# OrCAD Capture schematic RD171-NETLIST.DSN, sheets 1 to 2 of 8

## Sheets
1 8: size A3
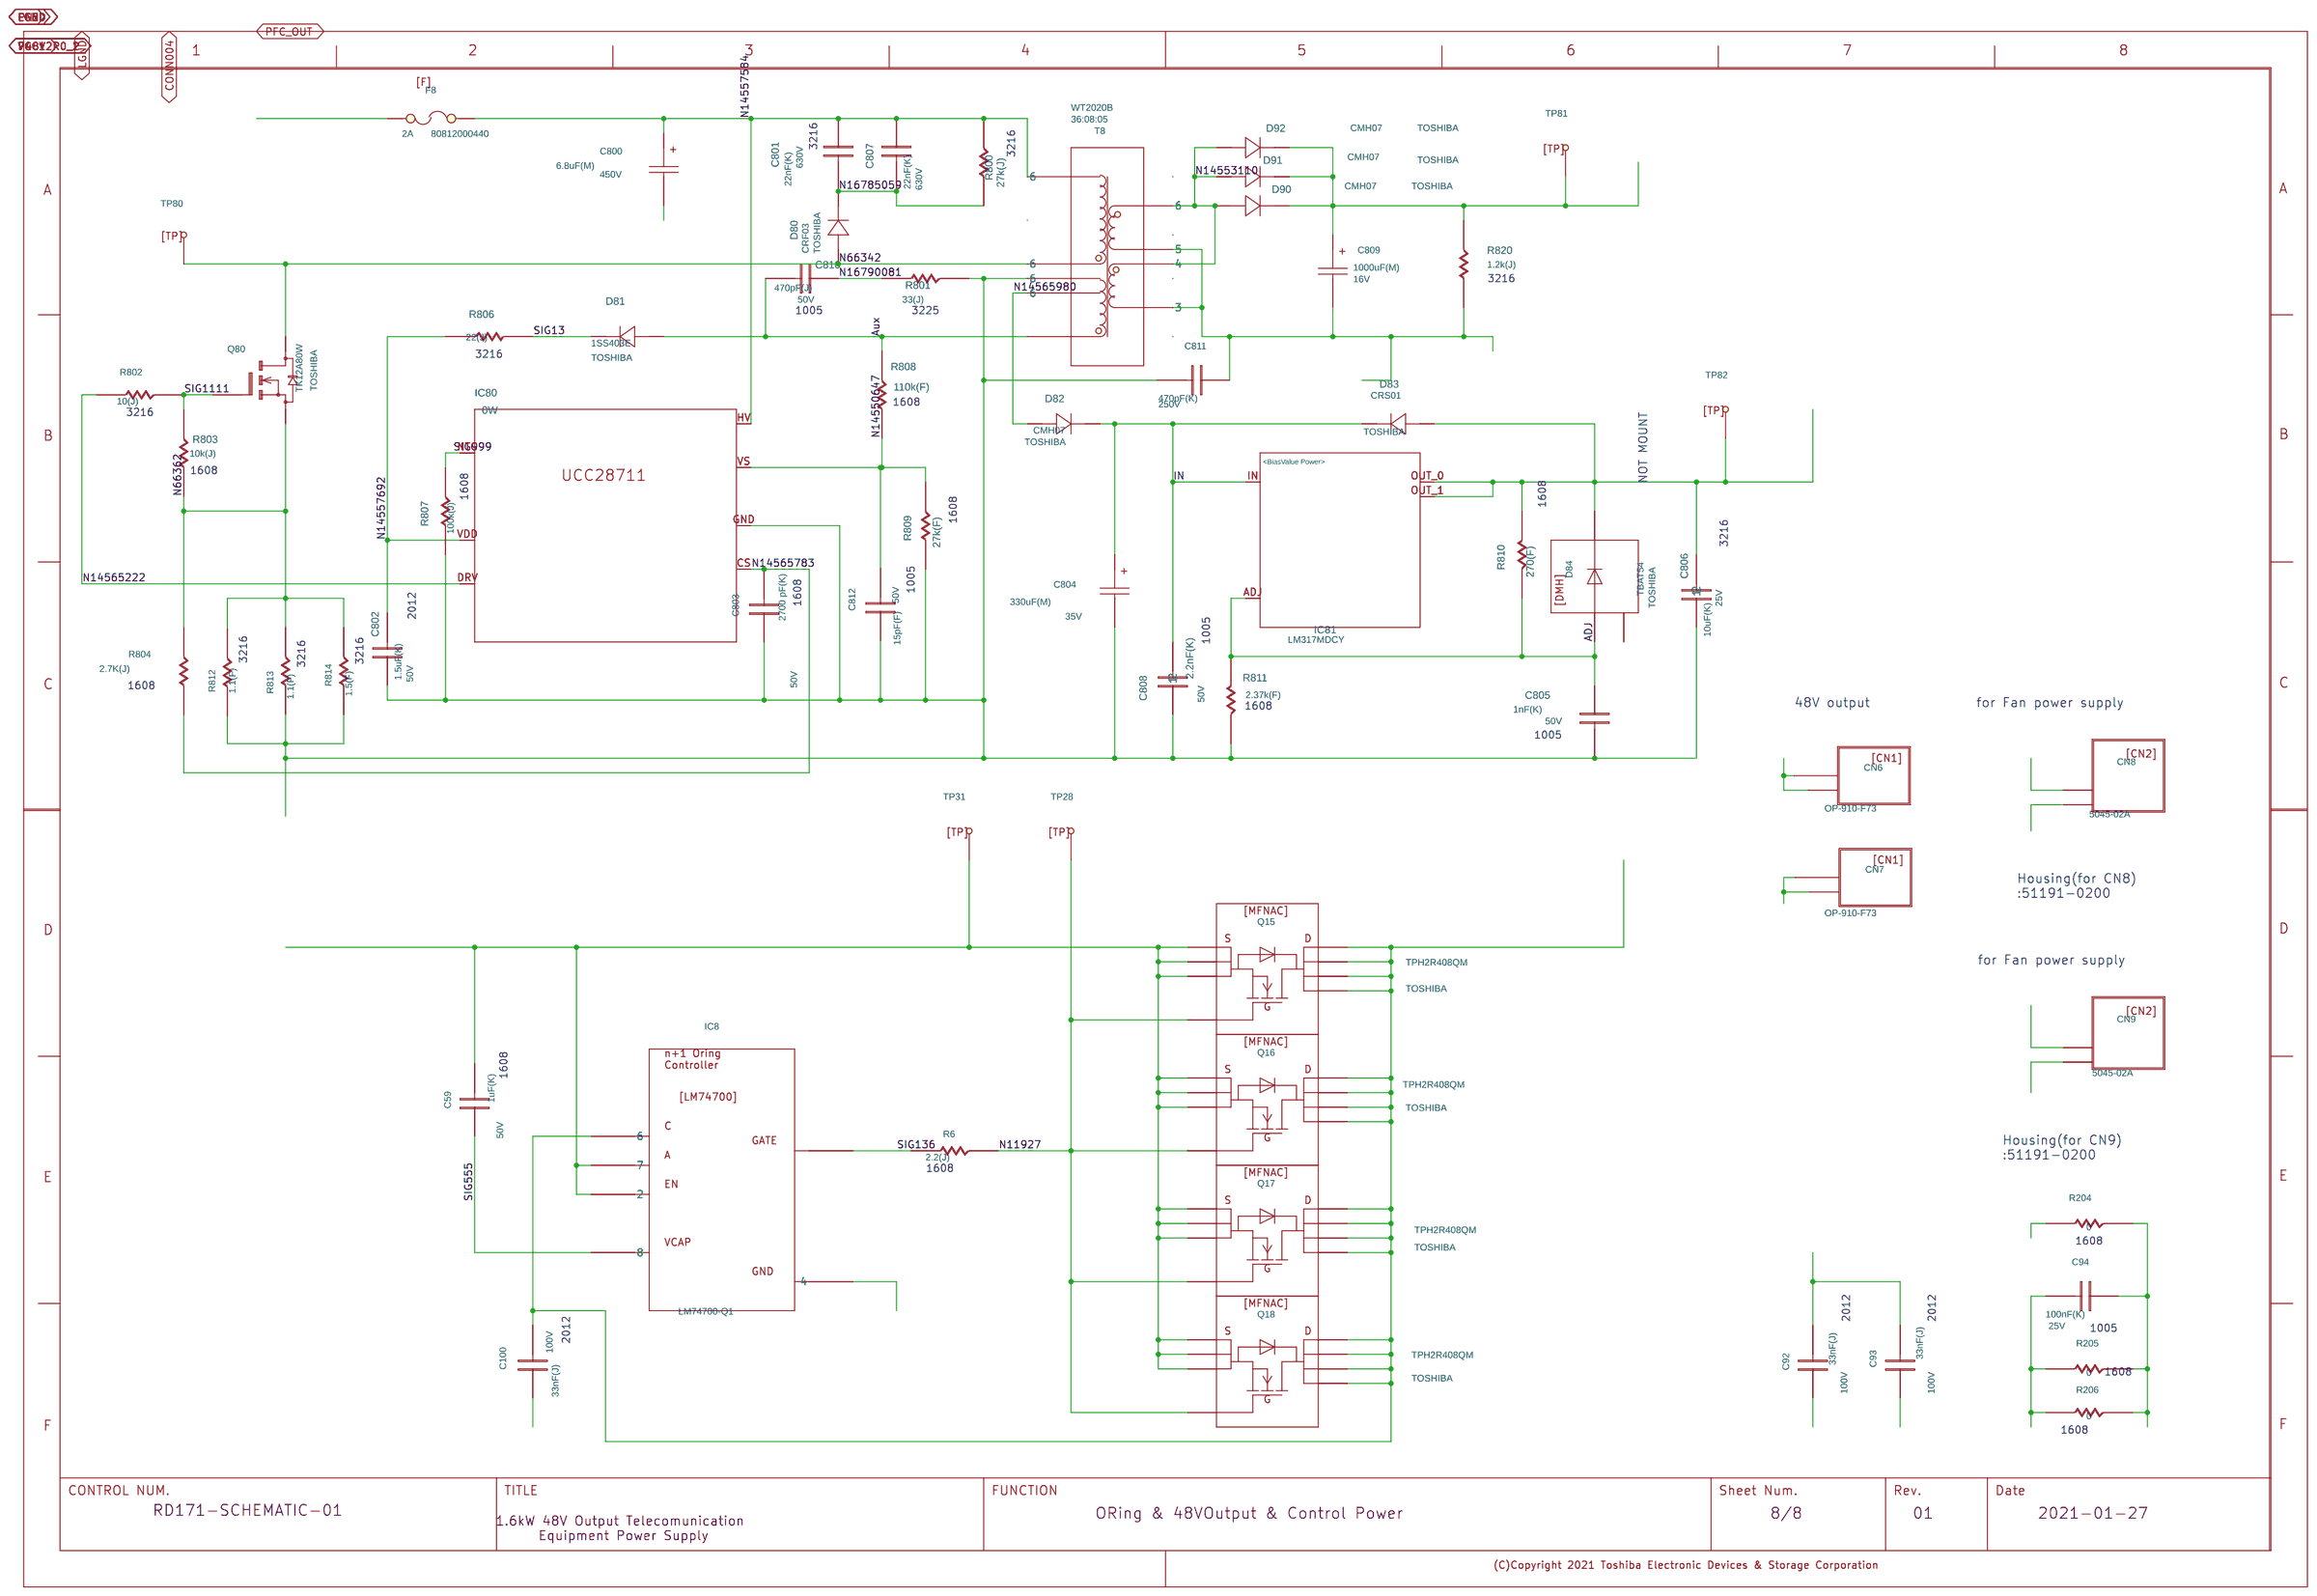
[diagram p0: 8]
2 7: size A3
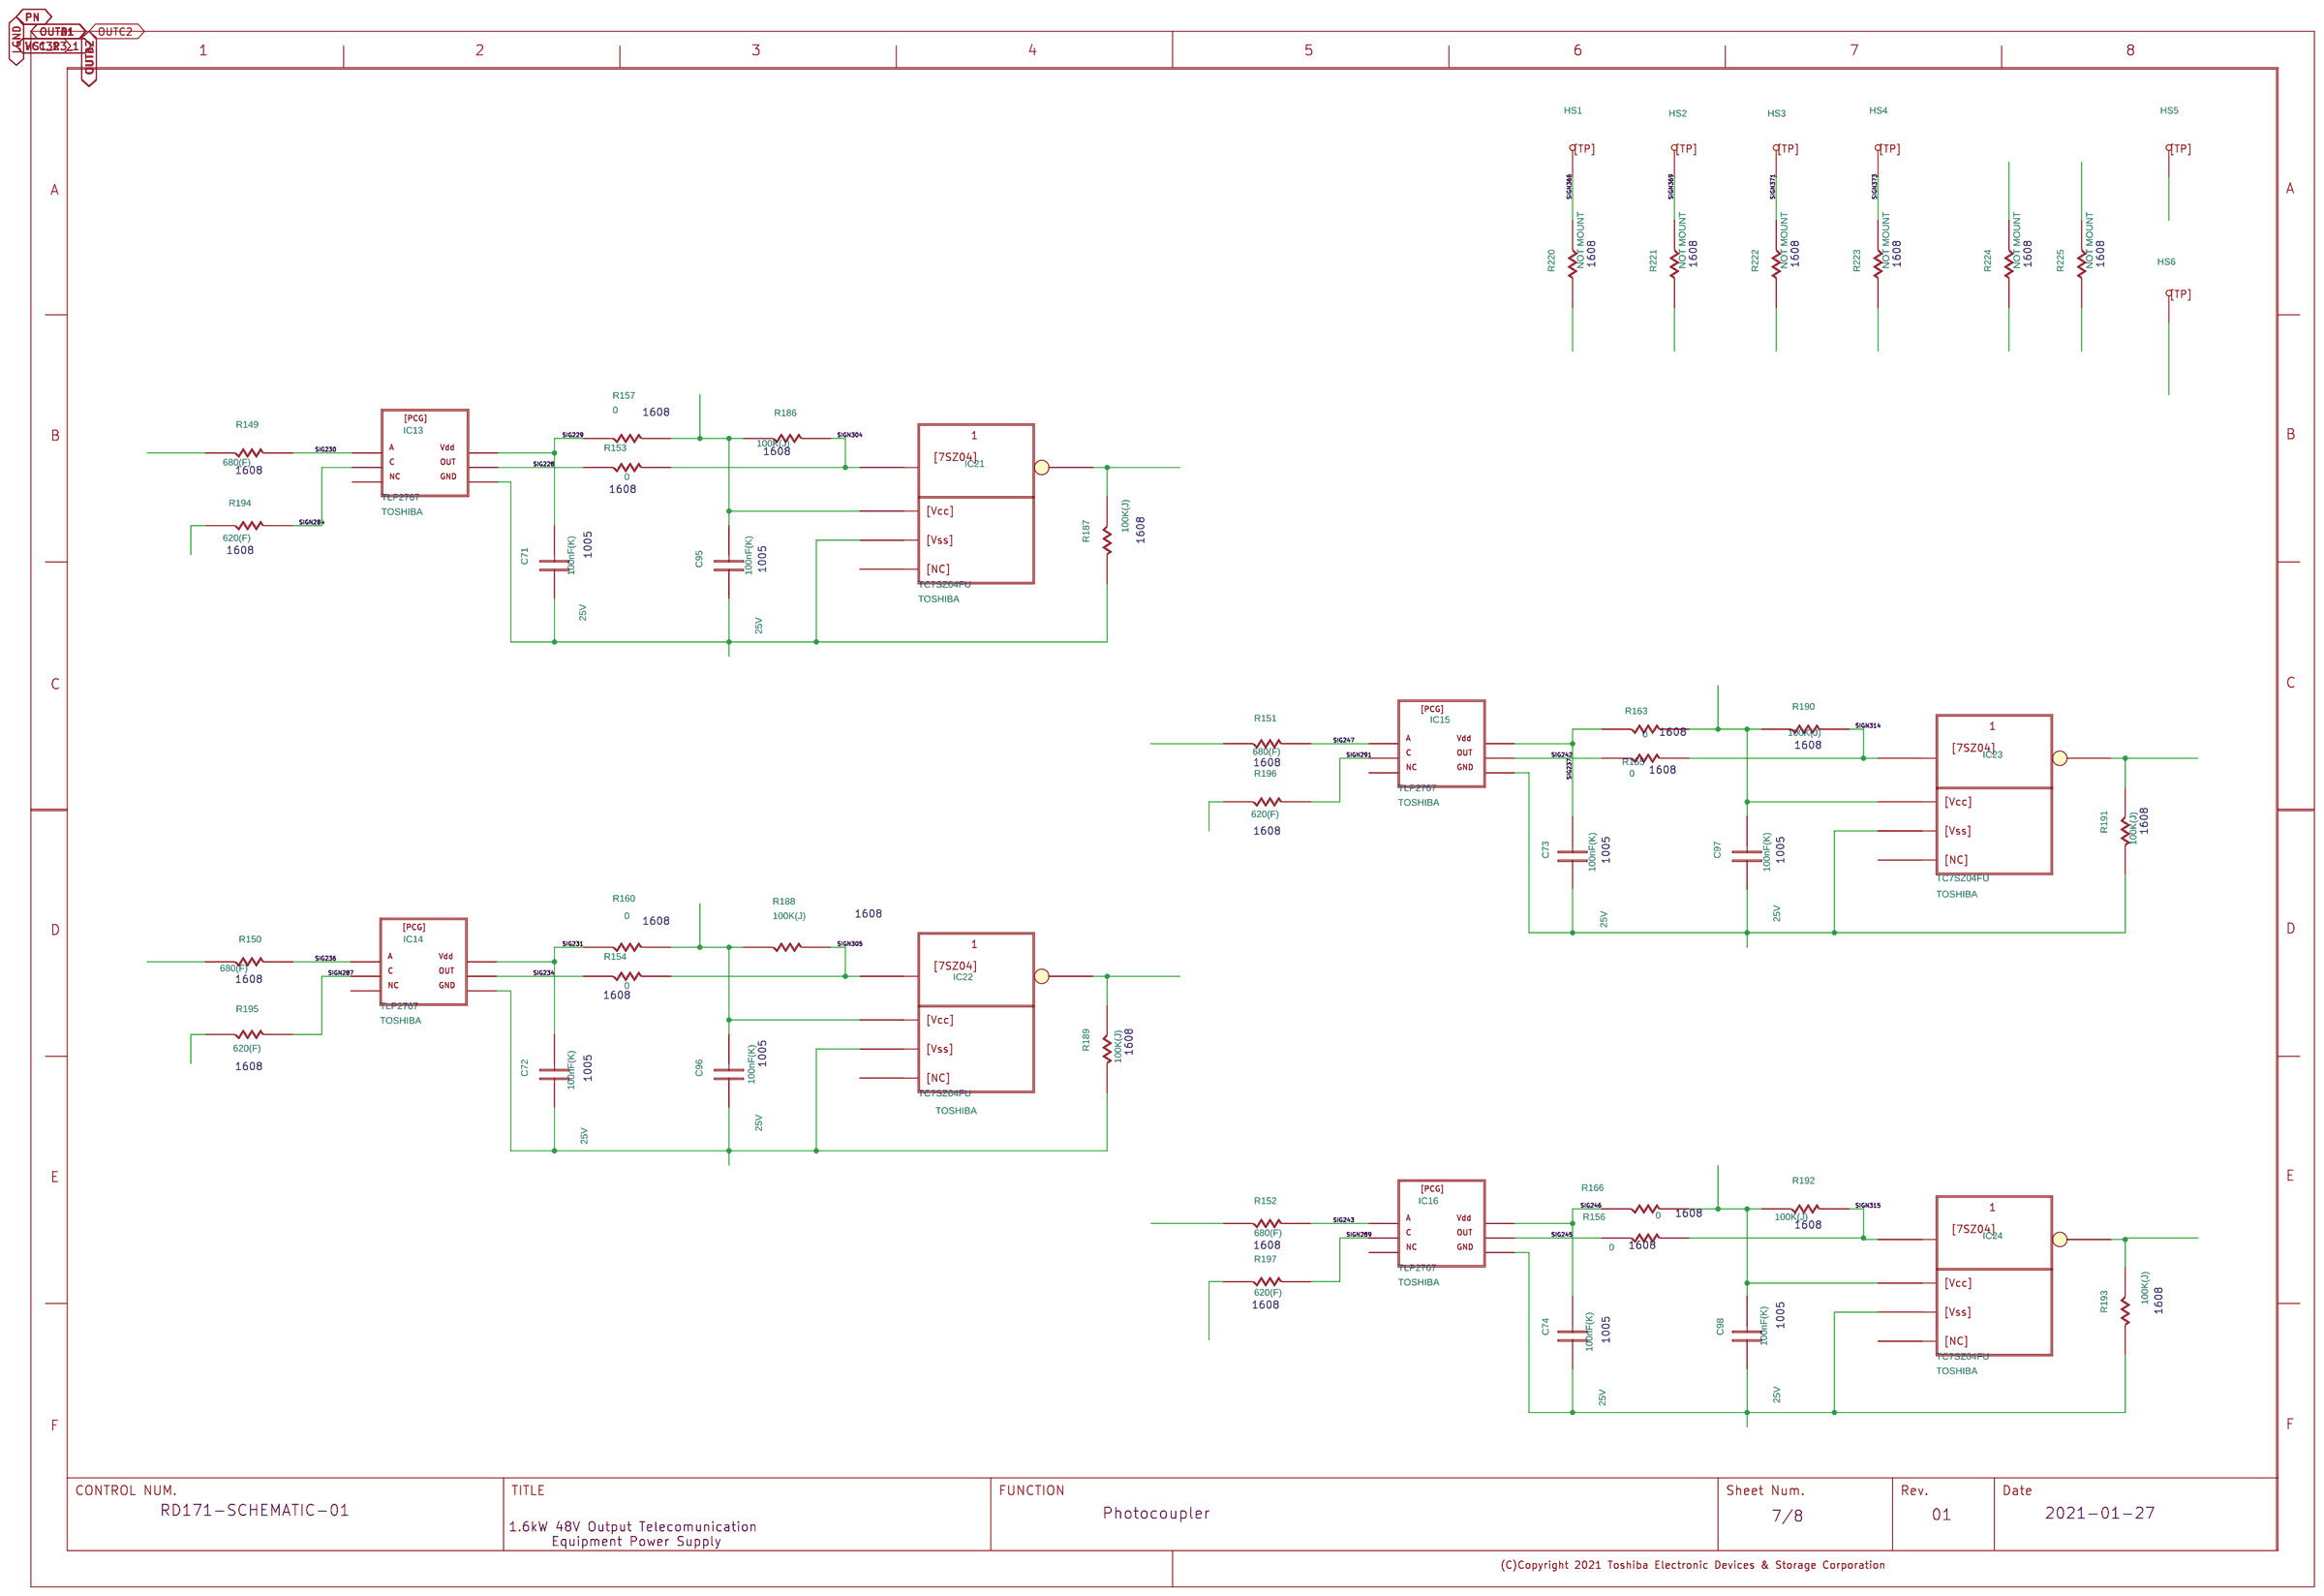
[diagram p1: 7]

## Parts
sheet 7
C71  100nF
C72  100nF
C73  100nF
C74  100nF
C95  100nF
C96  100nF
C97  100nF
C98  100nF
HS1  HS1  [HOLE2.8]
HS2  HS2  [HOLE2.8]
HS3  HS3  [HOLE2.8]
HS4  HS4  [HOLE2.8]
HS5  HS5  [HOLE2.0]
HS6  HS5  [HOLE2.0]
IC13  IC13  [TLP2767]
IC14  IC14  [TLP2767]
IC15  IC15  [TLP2767]
IC16  IC16  [TLP2767]
IC21  IC21  [TC7SZ04FU]
IC22  IC22  [TC7SZ04FU]
IC23  IC23  [TC7SZ04FU]
IC24  IC24  [TC7SZ04FU]
R149  680
R150  680
R151  680
R152  680
R153  0
R154  0
R155  0
R156  0
R157  0
R160  0
R163  0
R166  0
R186  100k
R187  100k
R188  100k
R189  100k
R190  100k
R191  100k
R192  100k
R193  100k
R194  620
R195  620
R196  620
R197  620
R220  0
R221  0
R222  0
R223  0
R224  0
R225  0
U?#1  WAKU_DEF100
sheet 8
C59  1uF  [C1608JB1H105K080AB]
C92  33nF  [C2012C0G2A333J125AE]
C93  33nF  [C2012C0G2A333J125AE]
C94  100nF
C100  33nF  [C2012C0G2A333J125AE]
C800  6.8uF  [EKXJ451ETD6R8MJ16S]
C801  22nF  [C3216X7R2J223K130AA]
C802  1.5uF  [C2012X7R1H155K125AC]
C803  2.7nF
C804  330uF  [EKZH350ETD331MJC5S]
C805  1nF
C806  10uF  [C3216X7R1E106K160AE]
C807  22nF  [C3216X7R2J223K130AA]
C808  2.2nF
C809  1000uF  [EKZH160ELL102MH20D]
C810  470pF  [C1005NP01H471J050BA]
C811  470pF  [DE2B3SA471KN3AT02F]
C812  NOT MOUNT
CN6  CN6  [OP-910-F73]
CN7  CN7
CN8  CN8  [5045-02A]
CN9  CN9  [5045-02A]
D80  D80  [CRF03]
D81  D81  [1SS403E]
D82  D82  [CMH07]
D83  D83  [CRS01]
D84  D84  [TBAT54]
D90  D90  [CMH07]
D91  D91  [CMH07]
D92  D92  [CMH07]
F8  2A  [80812000440]
IC8  IC8  [LM74700-Q1]
IC80  IC80  [UCC28711DR]
IC81  LM317_TRANS  [LM317MDCY]
Q15  Q15  [TPH2R408QM]
Q16  Q16  [TPH2R408QM]
Q17  Q17  [TPH2R408QM]
Q18  Q18  [TPH2R408QM]
Q80  Q80  [TK12A80W]
R6  2.2
R204  0
R205  0
R206  0
R800  27k  [MOS3CT631R273J]
R801  33  [RK73B2ETTD330J]
R802  10
R803  10k
R804  2.7k
R806  22
R807  100k
R808  110k
R809  27k
R810  270
R811  2.37k
R812  1.1  [RK73H2BTTD1R10F]
R813  1.1  [RK73H2BTTD1R10F]
R814  1.5  [RK73H2BTTD1R50F]
R820  1.2k
T8  T3_12V67A
TP28  TP28  [HK-2-S]
TP31  TP31  [HK-2-S]
TP80  TP80  [HK-2-S]
TP81  TP81  [HK-2-S]
TP82  TP82  [HK-2-S]
U?#8  WAKU_DEF100

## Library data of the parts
C71 = C: ADSCNVFLAG: ON; ADSCOMPONENTNAME: C_1005; ADSMODELNAME: s_GRM155R71E104KE14D; CAPACITANCETOLE: K; CDMASTERCADCELG: KC0005; CHIPSIZE: 1005; COMP: PRT_52; COMPONENTNAME: C_C.Normal_package; FNLEADFREETHET1GT2GMCTH1: N_N_N; FUNCTION: C_C.Normal_package; GCOUNT: 1; ICX_PART_MODEL: CON_100N; INSTANCENAME: INS10182; MAKER: TDK; MAXGCOUNT: 1; NOMINALCAPACITA: 100n; OUMECLASSIFICATION: ƒZƒ‰ƒ~ƒbƒNƒRƒ“ƒfƒ“ƒT; OUMEMAKER: MRT ºc»ì; OUMEMAKERKATAMEI: GRM155R71E104KE14D; PARTNAME: Chip1005_GS_2; QUADMODEL: CON_100N; RATEDVOLTAGE: 25; SIZECODESMD: 1005; SQ_PART_MODEL: CON_100N; VAL1: 100nF(K); VAL2: 25V; VAL3: C1005X7R1E104K050BB
C72 = C: ADSCNVFLAG: ON; ADSCOMPONENTNAME: C_1005; ADSMODELNAME: s_GRM155R71E104KE14D; CAPACITANCETOLE: K; CDMASTERCADCELG: KC0005; CHIPSIZE: 1005; COMP: PRT_52; COMPONENTNAME: C_C.Normal_package; FNLEADFREETHET1GT2GMCTH1: N_N_N; FUNCTION: C_C.Normal_package; GCOUNT: 1; ICX_PART_MODEL: CON_100N; INSTANCENAME: INS10192; MAKER: TDK; MAXGCOUNT: 1; NOMINALCAPACITA: 100n; OUMECLASSIFICATION: ƒZƒ‰ƒ~ƒbƒNƒRƒ“ƒfƒ“ƒT; OUMEMAKER: MRT ºc»ì; OUMEMAKERKATAMEI: GRM155R71E104KE14D; PARTNAME: Chip1005_GS_2; QUADMODEL: CON_100N; RATEDVOLTAGE: 25; SIZECODESMD: 1005; SQ_PART_MODEL: CON_100N; VAL1: 100nF(K); VAL2: 25V; VAL3: C1005X7R1E104K050BB
C73 = C: ADSCNVFLAG: ON; ADSCOMPONENTNAME: C_1005; ADSMODELNAME: s_GRM155R71E104KE14D; CAPACITANCETOLE: K; CDMASTERCADCELG: KC0005; CHIPSIZE: 1005; COMP: PRT_52; COMPONENTNAME: C_C.Normal_package; FNLEADFREETHET1GT2GMCTH1: N_N_N; FUNCTION: C_C.Normal_package; GCOUNT: 1; ICX_PART_MODEL: CON_100N; INSTANCENAME: INS10222; MAKER: TDK; MAXGCOUNT: 1; NOMINALCAPACITA: 100n; OUMECLASSIFICATION: ƒZƒ‰ƒ~ƒbƒNƒRƒ“ƒfƒ“ƒT; OUMEMAKER: MRT ºc»ì; OUMEMAKERKATAMEI: GRM155R71E104KE14D; PARTNAME: Chip1005_GS_2; QUADMODEL: CON_100N; RATEDVOLTAGE: 25; SIZECODESMD: 1005; SQ_PART_MODEL: CON_100N; VAL1: 100nF(K); VAL2: 25V; VAL3: C1005X7R1E104K050BB
C74 = C: ADSCNVFLAG: ON; ADSCOMPONENTNAME: C_1005; ADSMODELNAME: s_GRM155R71E104KE14D; CAPACITANCETOLE: K; CDMASTERCADCELG: KC0005; CHIPSIZE: 1005; COMP: PRT_52; COMPONENTNAME: C_C.Normal_package; FNLEADFREETHET1GT2GMCTH1: N_N_N; FUNCTION: C_C.Normal_package; GCOUNT: 1; ICX_PART_MODEL: CON_100N; INSTANCENAME: INS10252; MAKER: TDK; MAXGCOUNT: 1; NOMINALCAPACITA: 100n; OUMECLASSIFICATION: ƒZƒ‰ƒ~ƒbƒNƒRƒ“ƒfƒ“ƒT; OUMEMAKER: MRT ºc»ì; OUMEMAKERKATAMEI: GRM155R71E104KE14D; PARTNAME: Chip1005_GS_2; QUADMODEL: CON_100N; RATEDVOLTAGE: 25; SIZECODESMD: 1005; SQ_PART_MODEL: CON_100N; VAL1: 100nF(K); VAL2: 25V; VAL3: C1005X7R1E104K050BB
C95 = C: ADSCOMPONENTNAME: C_1005; ADSMODELNAME: s_GRM155R71E104KE14D; CAPACITANCETOLE: K; CHIPSIZE: 1005; COMP: PRT_52; COMPONENTNAME: C_C.Normal_package; FUNCTION: C_C.Normal_package; GCOUNT: 1; INSTANCENAME: INS10380; MAKER: TDK; MAXGCOUNT: 1; NOMINALCAPACITA: 100n; PARTNAME: Chip1005_GS_2; RATEDVOLTAGE: 25; SIZECODESMD: 1005; VAL1: 100nF(K); VAL2: 25V; VAL3: C1005X7R1E104K050BB
C96 = C: ADSCOMPONENTNAME: C_1005; ADSMODELNAME: s_GRM155R71E104KE14D; CAPACITANCETOLE: K; CHIPSIZE: 1005; COMP: PRT_52; COMPONENTNAME: C_C.Normal_package; FUNCTION: C_C.Normal_package; GCOUNT: 1; INSTANCENAME: INS10448; MAKER: TDK; MAXGCOUNT: 1; NOMINALCAPACITA: 100n; PARTNAME: Chip1005_GS_2; RATEDVOLTAGE: 25; SIZECODESMD: 1005; VAL1: 100nF(K); VAL2: 25V; VAL3: C1005X7R1E104K050BB
C97 = C: ADSCOMPONENTNAME: C_1005; ADSMODELNAME: s_GRM155R71E104KE14D; CAPACITANCETOLE: K; CHIPSIZE: 1005; COMP: PRT_52; COMPONENTNAME: C_C.Normal_package; FUNCTION: C_C.Normal_package; GCOUNT: 1; INSTANCENAME: INS10544; MAKER: TDK; MAXGCOUNT: 1; NOMINALCAPACITA: 100n; PARTNAME: Chip1005_GS_2; RATEDVOLTAGE: 25; SIZECODESMD: 1005; VAL1: 100nF(K); VAL2: 25V; VAL3: C1005X7R1E104K050BB
C98 = C: ADSCOMPONENTNAME: C_1005; ADSMODELNAME: s_GRM155R71E104KE14D; CAPACITANCETOLE: K; CHIPSIZE: 1005; COMP: PRT_52; COMPONENTNAME: C_C.Normal_package; FUNCTION: C_C.Normal_package; GCOUNT: 1; INSTANCENAME: INS10534; MAKER: TDK; MAXGCOUNT: 1; NOMINALCAPACITA: 100n; PARTNAME: Chip1005_GS_2; RATEDVOLTAGE: 25; SIZECODESMD: 1005; VAL1: 100nF(K); VAL2: 25V; VAL3: C1005X7R1E104K050BB
HS1 = TP: CHIPSIZE: Through Hole; COMP: PRT_39; COMPONENTNAME: TP_TP.Normal_package; FUNCTION: TP_TP.Normal_package; INSTANCENAME: INS10726; PARTNAME: TP_I_TH2.8_TBLC3.8_ILC0_RC3.9_GS
HS2 = TP: CHIPSIZE: Through Hole; COMP: PRT_39; COMPONENTNAME: TP_TP.Normal_package; FUNCTION: TP_TP.Normal_package; INSTANCENAME: INS10734; PARTNAME: TP_I_TH2.8_TBLC3.8_ILC0_RC3.9_GS
HS3 = TP: CHIPSIZE: Through Hole; COMP: PRT_39; COMPONENTNAME: TP_TP.Normal_package; FUNCTION: TP_TP.Normal_package; INSTANCENAME: INS10742; PARTNAME: TP_I_TH2.8_TBLC3.8_ILC0_RC3.9_GS
HS4 = TP: CHIPSIZE: Through Hole; COMP: PRT_39; COMPONENTNAME: TP_TP.Normal_package; FUNCTION: TP_TP.Normal_package; INSTANCENAME: INS10750; PARTNAME: TP_I_TH2.8_TBLC3.8_ILC0_RC3.9_GS
HS5 = TP: CHIPSIZE: Through Hole; COMP: PRT_39; COMPONENTNAME: TP_TP.Normal_package; FUNCTION: TP_TP.Normal_package; INSTANCENAME: INS17030042; PARTNAME: BPUS15-25_GS; VAL3: BPUS15-25
HS6 = TP: CHIPSIZE: Through Hole; COMP: PRT_39; COMPONENTNAME: TP_TP.Normal_package; FUNCTION: TP_TP.Normal_package; INSTANCENAME: INS17030123; PARTNAME: BPUS15-25_GS; VAL3: BPUS15-25
IC13 = PCG6PIN: COMP: PRT_15; COMPONENTNAME: PCG6PIN_PCG6PIN.Normal_package; FUNCTION: PCG6PIN_PCG6PIN.Normal_package; INSTANCENAME: INS10674; MAKER: TOSHIBA; PARTNAME: TLP2767_TS; USERCOMPTEXT3: TOSHIBA
IC14 = PCG6PIN: COMP: PRT_15; COMPONENTNAME: PCG6PIN_PCG6PIN.Normal_package; FUNCTION: PCG6PIN_PCG6PIN.Normal_package; INSTANCENAME: INS10614; MAKER: TOSHIBA; PARTNAME: TLP2767_TS; USERCOMPTEXT3: TOSHIBA
IC15 = PCG6PIN: COMP: PRT_15; COMPONENTNAME: PCG6PIN_PCG6PIN.Normal_package; FUNCTION: PCG6PIN_PCG6PIN.Normal_package; INSTANCENAME: INS10634; MAKER: TOSHIBA; PARTNAME: TLP2767_TS; USERCOMPTEXT3: TOSHIBA
IC16 = PCG6PIN: COMP: PRT_15; COMPONENTNAME: PCG6PIN_PCG6PIN.Normal_package; FUNCTION: PCG6PIN_PCG6PIN.Normal_package; INSTANCENAME: INS10654; MAKER: TOSHIBA; PARTNAME: TLP2767_TS; USERCOMPTEXT3: TOSHIBA
IC21 = 7SZ04: COMP: PRT_2; COMPONENTNAME: 7SZ04_7SZ04.Normal_package; FUNCTION: 7SZ04_7SZ04.Normal_package; INSTANCENAME: INS10362; MAKER: TOSHIBA; PARTNAME: TC7SZ04FU_TS_1; SAVECOUNT: 1; UPDATEDATE: 2020/07/08; UPDATETIME: 16:40:05; USERCOMPTEXT3: TOSHIBA
IC22 = 7SZ04: COMP: PRT_2; COMPONENTNAME: 7SZ04_7SZ04.Normal_package; FUNCTION: 7SZ04_7SZ04.Normal_package; INSTANCENAME: INS10420; MAKER: TOSHIBA; PARTNAME: TC7SZ04FU_TS_1; SAVECOUNT: 1; UPDATEDATE: 2020/07/08; UPDATETIME: 16:40:05; USERCOMPTEXT3: TOSHIBA
IC23 = 7SZ04: COMP: PRT_2; COMPONENTNAME: 7SZ04_7SZ04.Normal_package; FUNCTION: 7SZ04_7SZ04.Normal_package; INSTANCENAME: INS10468; MAKER: TOSHIBA; PARTNAME: TC7SZ04FU_TS_1; SAVECOUNT: 1; UPDATEDATE: 2020/07/08; UPDATETIME: 16:40:05; USERCOMPTEXT3: TOSHIBA
IC24 = 7SZ04: COMP: PRT_2; COMPONENTNAME: 7SZ04_7SZ04.Normal_package; FUNCTION: 7SZ04_7SZ04.Normal_package; INSTANCENAME: INS10516; MAKER: TOSHIBA; PARTNAME: TC7SZ04FU_TS_1; SAVECOUNT: 1; UPDATEDATE: 2020/07/08; UPDATETIME: 16:40:05; USERCOMPTEXT3: TOSHIBA
R149 = R: CHIPSIZE: 1608; COMP: PRT_8; COMPONENTNAME: R_R.Normal_package; FUNCTION: R_R.Normal_package; INSTANCENAME: INS10282; MAKER: KOA; PARTNAME: Chip1608_GS_1; VAL1: 680(F); VAL2: 100mW; VAL3: RK73H1JTTD6800F
R150 = R: CHIPSIZE: 1608; COMP: PRT_8; COMPONENTNAME: R_R.Normal_package; FUNCTION: R_R.Normal_package; INSTANCENAME: INS10292; MAKER: KOA; PARTNAME: Chip1608_GS_1; VAL1: 680(F); VAL2: 100mW; VAL3: RK73H1JTTD6800F
R151 = R: CHIPSIZE: 1608; COMP: PRT_8; COMPONENTNAME: R_R.Normal_package; FUNCTION: R_R.Normal_package; INSTANCENAME: INS10302; MAKER: KOA; PARTNAME: Chip1608_GS_1; VAL1: 680(F); VAL2: 100mW; VAL3: RK73H1JTTD6800F
R152 = R: CHIPSIZE: 1608; COMP: PRT_8; COMPONENTNAME: R_R.Normal_package; FUNCTION: R_R.Normal_package; INSTANCENAME: INS10312; MAKER: KOA; PARTNAME: Chip1608_GS_1; VAL1: 680(F); VAL2: 100mW; VAL3: RK73H1JTTD6800F
R153 = R: ADSCNVFLAG: ON; ADSCOMPONENTNAME: R_1005; ADSMODELNAME: s_ERJ2GE0R00X; CDMASTERCADCELG: KC0005; CHIPSIZE: 1608; COMP: PRT_8; COMPONENTNAME: R_R.Normal_package; FNLEADFREETHET1GT2GMCTH1: 2_1_N; FUNCTION: R_R.Normal_package; GCOUNT: 1; ICX_PART_MODEL: RES_0; INSTANCENAME: INS10162; MAKER: KOA; MAXGCOUNT: 1; MOUNTINGFORMSMD: SMD; OUMECLASSIFICATION: \ÊÀpÅèïRí; OUMEMAKER: NAE pi\jbNGNgjbNfoCX; OUMEMAKERKATAMEI: ERJ2GE0R00X; PARTNAME: Chip1608_GS_1; PMPRODUCTSTYPEG: HD1-PC1; POWERRATING: 63m; QUADMODEL: RES_0; RESISTANCETOLER: X; SIZECODESMD: 1005; SQ_PART_MODEL: RES_0; VAL2: 100mW; VAL3: RK73Z1JTTD
R154 = R: ADSCNVFLAG: ON; ADSCOMPONENTNAME: R_1005; ADSMODELNAME: s_ERJ2GE0R00X; CDMASTERCADCELG: KC0005; CHIPSIZE: 1608; COMP: PRT_8; COMPONENTNAME: R_R.Normal_package; FNLEADFREETHET1GT2GMCTH1: 2_1_N; FUNCTION: R_R.Normal_package; GCOUNT: 1; ICX_PART_MODEL: RES_0; INSTANCENAME: INS10212; MAKER: KOA; MAXGCOUNT: 1; MOUNTINGFORMSMD: SMD; OUMECLASSIFICATION: \ÊÀpÅèïRí; OUMEMAKER: NAE pi\jbNGNgjbNfoCX; OUMEMAKERKATAMEI: ERJ2GE0R00X; PARTNAME: Chip1608_GS_1; PMPRODUCTSTYPEG: HD1-PC1; POWERRATING: 63m; QUADMODEL: RES_0; RESISTANCETOLER: X; SIZECODESMD: 1005; SQ_PART_MODEL: RES_0; VAL2: 100mW; VAL3: RK73Z1JTTD
R155 = R: ADSCNVFLAG: ON; ADSCOMPONENTNAME: R_1005; ADSMODELNAME: s_ERJ2GE0R00X; CDMASTERCADCELG: KC0005; CHIPSIZE: 1608; COMP: PRT_8; COMPONENTNAME: R_R.Normal_package; FNLEADFREETHET1GT2GMCTH1: 2_1_N; FUNCTION: R_R.Normal_package; GCOUNT: 1; ICX_PART_MODEL: RES_0; INSTANCENAME: INS10262; MAKER: KOA; MAXGCOUNT: 1; MOUNTINGFORMSMD: SMD; OUMECLASSIFICATION: \ÊÀpÅèïRí; OUMEMAKER: NAE pi\jbNGNgjbNfoCX; OUMEMAKERKATAMEI: ERJ2GE0R00X; PARTNAME: Chip1608_GS_1; PMPRODUCTSTYPEG: HD1-PC1; POWERRATING: 63m; QUADMODEL: RES_0; RESISTANCETOLER: X; SIZECODESMD: 1005; SQ_PART_MODEL: RES_0; VAL2: 100mW; VAL3: RK73Z1JTTD
R156 = R: ADSCNVFLAG: ON; ADSCOMPONENTNAME: R_1005; ADSMODELNAME: s_ERJ2GE0R00X; CDMASTERCADCELG: KC0005; CHIPSIZE: 1608; COMP: PRT_8; COMPONENTNAME: R_R.Normal_package; FNLEADFREETHET1GT2GMCTH1: 2_1_N; FUNCTION: R_R.Normal_package; GCOUNT: 1; ICX_PART_MODEL: RES_0; INSTANCENAME: INS10242; MAKER: KOA; MAXGCOUNT: 1; MOUNTINGFORMSMD: SMD; OUMECLASSIFICATION: \ÊÀpÅèïRí; OUMEMAKER: NAE pi\jbNGNgjbNfoCX; OUMEMAKERKATAMEI: ERJ2GE0R00X; PARTNAME: Chip1608_GS_1; PMPRODUCTSTYPEG: HD1-PC1; POWERRATING: 63m; QUADMODEL: RES_0; RESISTANCETOLER: X; SIZECODESMD: 1005; SQ_PART_MODEL: RES_0; VAL2: 100mW; VAL3: RK73Z1JTTD
R157 = R: ADSCNVFLAG: ON; ADSCOMPONENTNAME: R_1005; ADSMODELNAME: s_ERJ2GE0R00X; CDMASTERCADCELG: KC0005; CHIPSIZE: 1608; COMP: PRT_8; COMPONENTNAME: R_R.Normal_package; FNLEADFREETHET1GT2GMCTH1: 2_1_N; FUNCTION: R_R.Normal_package; GCOUNT: 1; ICX_PART_MODEL: RES_0; INSTANCENAME: INS10172; MAKER: KOA; MAXGCOUNT: 1; MOUNTINGFORMSMD: SMD; OUMECLASSIFICATION: \ÊÀpÅèïRí; OUMEMAKER: NAE pi\jbNGNgjbNfoCX; OUMEMAKERKATAMEI: ERJ2GE0R00X; PARTNAME: Chip1608_GS_1; PMPRODUCTSTYPEG: HD1-PC1; POWERRATING: 63m; QUADMODEL: RES_0; RESISTANCETOLER: X; SIZECODESMD: 1005; SQ_PART_MODEL: RES_0; VAL2: 100mW; VAL3: RK73Z1JTTD
R160 = R: ADSCNVFLAG: ON; ADSCOMPONENTNAME: R_1005; ADSMODELNAME: s_ERJ2GE0R00X; CDMASTERCADCELG: KC0005; CHIPSIZE: 1608; COMP: PRT_8; COMPONENTNAME: R_R.Normal_package; FNLEADFREETHET1GT2GMCTH1: 2_1_N; FUNCTION: R_R.Normal_package; GCOUNT: 1; ICX_PART_MODEL: RES_0; INSTANCENAME: INS10202; MAKER: KOA; MAXGCOUNT: 1; MOUNTINGFORMSMD: SMD; OUMECLASSIFICATION: \ÊÀpÅèïRí; OUMEMAKER: NAE pi\jbNGNgjbNfoCX; OUMEMAKERKATAMEI: ERJ2GE0R00X; PARTNAME: Chip1608_GS_1; PMPRODUCTSTYPEG: HD1-PC1; POWERRATING: 63m; QUADMODEL: RES_0; RESISTANCETOLER: X; SIZECODESMD: 1005; SQ_PART_MODEL: RES_0; VAL2: 100mW; VAL3: RK73Z1JTTD
R163 = R: ADSCNVFLAG: ON; ADSCOMPONENTNAME: R_1005; ADSMODELNAME: s_ERJ2GE0R00X; CDMASTERCADCELG: KC0005; CHIPSIZE: 1608; COMP: PRT_8; COMPONENTNAME: R_R.Normal_package; FNLEADFREETHET1GT2GMCTH1: 2_1_N; FUNCTION: R_R.Normal_package; GCOUNT: 1; ICX_PART_MODEL: RES_0; INSTANCENAME: INS10232; MAKER: KOA; MAXGCOUNT: 1; MOUNTINGFORMSMD: SMD; OUMECLASSIFICATION: \ÊÀpÅèïRí; OUMEMAKER: NAE pi\jbNGNgjbNfoCX; OUMEMAKERKATAMEI: ERJ2GE0R00X; PARTNAME: Chip1608_GS_1; PMPRODUCTSTYPEG: HD1-PC1; POWERRATING: 63m; QUADMODEL: RES_0; RESISTANCETOLER: X; SIZECODESMD: 1005; SQ_PART_MODEL: RES_0; VAL2: 100mW; VAL3: RK73Z1JTTD
R166 = R: ADSCNVFLAG: ON; ADSCOMPONENTNAME: R_1005; ADSMODELNAME: s_ERJ2GE0R00X; CDMASTERCADCELG: KC0005; CHIPSIZE: 1608; COMP: PRT_8; COMPONENTNAME: R_R.Normal_package; FNLEADFREETHET1GT2GMCTH1: 2_1_N; FUNCTION: R_R.Normal_package; GCOUNT: 1; ICX_PART_MODEL: RES_0; INSTANCENAME: INS10272; MAKER: KOA; MAXGCOUNT: 1; MOUNTINGFORMSMD: SMD; OUMECLASSIFICATION: \ÊÀpÅèïRí; OUMEMAKER: NAE pi\jbNGNgjbNfoCX; OUMEMAKERKATAMEI: ERJ2GE0R00X; PARTNAME: Chip1608_GS_1; PMPRODUCTSTYPEG: HD1-PC1; POWERRATING: 63m; QUADMODEL: RES_0; RESISTANCETOLER: X; SIZECODESMD: 1005; SQ_PART_MODEL: RES_0; VAL2: 100mW; VAL3: RK73Z1JTTD
R186 = R: CHIPSIZE: 1608; COMP: PRT_8; COMPONENTNAME: R_R.Normal_package; FUNCTION: R_R.Normal_package; INSTANCENAME: INS10390; MAKER: KOA; PARTNAME: Chip1608_GS_1; VAL1: 100K(J); VAL2: 100mW,}5%; VAL3: RK73B1JTTD104J
R187 = R: CHIPSIZE: 1608; COMP: PRT_8; COMPONENTNAME: R_R.Normal_package; FUNCTION: R_R.Normal_package; INSTANCENAME: INS10400; MAKER: KOA; PARTNAME: Chip1608_GS_1; VAL1: 100K(J); VAL2: 100mW,}5%; VAL3: RK73B1JTTD104J
R188 = R: CHIPSIZE: 1608; COMP: PRT_8; COMPONENTNAME: R_R.Normal_package; FUNCTION: R_R.Normal_package; INSTANCENAME: INS10410; MAKER: KOA; PARTNAME: Chip1608_GS_1; VAL1: 100K(J); VAL2: 100mW,}5%; VAL3: RK73B1JTTD104J
R189 = R: CHIPSIZE: 1608; COMP: PRT_8; COMPONENTNAME: R_R.Normal_package; FUNCTION: R_R.Normal_package; INSTANCENAME: INS10438; MAKER: KOA; PARTNAME: Chip1608_GS_1; VAL1: 100K(J); VAL2: 100mW,}5%; VAL3: RK73B1JTTD104J
R190 = R: CHIPSIZE: 1608; COMP: PRT_8; COMPONENTNAME: R_R.Normal_package; FUNCTION: R_R.Normal_package; INSTANCENAME: INS10458; MAKER: KOA; PARTNAME: Chip1608_GS_1; VAL1: 100K(J); VAL2: 100mW,}5%; VAL3: RK73B1JTTD104J
R191 = R: CHIPSIZE: 1608; COMP: PRT_8; COMPONENTNAME: R_R.Normal_package; FUNCTION: R_R.Normal_package; INSTANCENAME: INS10486; MAKER: KOA; PARTNAME: Chip1608_GS_1; VAL1: 100K(J); VAL2: 100mW,}5%; VAL3: RK73B1JTTD104J
R192 = R: CHIPSIZE: 1608; COMP: PRT_8; COMPONENTNAME: R_R.Normal_package; FUNCTION: R_R.Normal_package; INSTANCENAME: INS10506; MAKER: KOA; PARTNAME: Chip1608_GS_1; VAL1: 100K(J); VAL2: 100mW,}5%; VAL3: RK73B1JTTD104J
R193 = R: CHIPSIZE: 1608; COMP: PRT_8; COMPONENTNAME: R_R.Normal_package; FUNCTION: R_R.Normal_package; INSTANCENAME: INS10496; MAKER: KOA; PARTNAME: Chip1608_GS_1; VAL1: 100K(J); VAL2: 100mW,}5%; VAL3: RK73B1JTTD104J
R194 = R: CHIPSIZE: 1608; COMP: PRT_8; COMPONENTNAME: R_R.Normal_package; FUNCTION: R_R.Normal_package; INSTANCENAME: INS10322; MAKER: PANASONIC; PARTNAME: Chip1608_GS_1; VAL1: 620(F); VAL2: 100mW; VAL3: ERJ-3EKF6200V
R195 = R: CHIPSIZE: 1608; COMP: PRT_8; COMPONENTNAME: R_R.Normal_package; FUNCTION: R_R.Normal_package; INSTANCENAME: INS10332; MAKER: PANASONIC; PARTNAME: Chip1608_GS_1; VAL1: 620(F); VAL2: 100mW; VAL3: ERJ-3EKF6200V
R196 = R: CHIPSIZE: 1608; COMP: PRT_8; COMPONENTNAME: R_R.Normal_package; FUNCTION: R_R.Normal_package; INSTANCENAME: INS10352; MAKER: PANASONIC; PARTNAME: Chip1608_GS_1; VAL1: 620(F); VAL2: 100mW; VAL3: ERJ-3EKF6200V
R197 = R: CHIPSIZE: 1608; COMP: PRT_8; COMPONENTNAME: R_R.Normal_package; FUNCTION: R_R.Normal_package; INSTANCENAME: INS10342; MAKER: PANASONIC; PARTNAME: Chip1608_GS_1; VAL1: 620(F); VAL2: 100mW; VAL3: ERJ-3EKF6200V
R220 = R: ADSCNVFLAG: ON; ADSCOMPONENTNAME: R_1005; ADSMODELNAME: s_CR10_000V; CDMASTERCADCELG: KC0005; CHIPSIZE: 1608; COMP: PRT_8; COMPONENTNAME: R_R.Normal_package; FNLEADFREETHET1GT2GMCTH1: N_N_N; FUNCTION: R_R.Normal_package; GCOUNT: 1; ICX_PART_MODEL: RES_0; INSTANCENAME: INS10554; MAKER: KOA; MAXGCOUNT: 1; MOUNTINGFORMSMD: SMD; NOTMOUNT: NOT MOUNT; OUMECLASSIFICATION: \ÊÀpÅèïRí; OUMEMAKER: HDK k¤dCHÆ; OUMEMAKERKATAMEI: CR10-000V; PARTNAME: Chip1608_GS_1; POWERRATING: 63m; QUADMODEL: RES_0; RESISTANCETOLER: X; SIZECODESMD: 1005; SQ_PART_MODEL: RES_0; VAL2: 100mW; VAL3: RK73Z1JTTD
R221 = R: ADSCNVFLAG: ON; ADSCOMPONENTNAME: R_1005; ADSMODELNAME: s_CR10_000V; CDMASTERCADCELG: KC0005; CHIPSIZE: 1608; COMP: PRT_8; COMPONENTNAME: R_R.Normal_package; FNLEADFREETHET1GT2GMCTH1: N_N_N; FUNCTION: R_R.Normal_package; GCOUNT: 1; ICX_PART_MODEL: RES_0; INSTANCENAME: INS10564; MAKER: KOA; MAXGCOUNT: 1; MOUNTINGFORMSMD: SMD; NOTMOUNT: NOT MOUNT; OUMECLASSIFICATION: \ÊÀpÅèïRí; OUMEMAKER: HDK k¤dCHÆ; OUMEMAKERKATAMEI: CR10-000V; PARTNAME: Chip1608_GS_1; POWERRATING: 63m; QUADMODEL: RES_0; RESISTANCETOLER: X; SIZECODESMD: 1005; SQ_PART_MODEL: RES_0; VAL2: 100mW; VAL3: RK73Z1JTTD
R222 = R: ADSCNVFLAG: ON; ADSCOMPONENTNAME: R_1005; ADSMODELNAME: s_CR10_000V; CDMASTERCADCELG: KC0005; CHIPSIZE: 1608; COMP: PRT_8; COMPONENTNAME: R_R.Normal_package; FNLEADFREETHET1GT2GMCTH1: N_N_N; FUNCTION: R_R.Normal_package; GCOUNT: 1; ICX_PART_MODEL: RES_0; INSTANCENAME: INS10574; MAKER: KOA; MAXGCOUNT: 1; MOUNTINGFORMSMD: SMD; NOTMOUNT: NOT MOUNT; OUMECLASSIFICATION: \ÊÀpÅèïRí; OUMEMAKER: HDK k¤dCHÆ; OUMEMAKERKATAMEI: CR10-000V; PARTNAME: Chip1608_GS_1; POWERRATING: 63m; QUADMODEL: RES_0; RESISTANCETOLER: X; SIZECODESMD: 1005; SQ_PART_MODEL: RES_0; VAL2: 100mW; VAL3: RK73Z1JTTD
R223 = R: ADSCNVFLAG: ON; ADSCOMPONENTNAME: R_1005; ADSMODELNAME: s_CR10_000V; CDMASTERCADCELG: KC0005; CHIPSIZE: 1608; COMP: PRT_8; COMPONENTNAME: R_R.Normal_package; FNLEADFREETHET1GT2GMCTH1: N_N_N; FUNCTION: R_R.Normal_package; GCOUNT: 1; ICX_PART_MODEL: RES_0; INSTANCENAME: INS10584; MAKER: KOA; MAXGCOUNT: 1; MOUNTINGFORMSMD: SMD; NOTMOUNT: NOT MOUNT; OUMECLASSIFICATION: \ÊÀpÅèïRí; OUMEMAKER: HDK k¤dCHÆ; OUMEMAKERKATAMEI: CR10-000V; PARTNAME: Chip1608_GS_1; POWERRATING: 63m; QUADMODEL: RES_0; RESISTANCETOLER: X; SIZECODESMD: 1005; SQ_PART_MODEL: RES_0; VAL2: 100mW; VAL3: RK73Z1JTTD
R224 = R: ADSCNVFLAG: ON; ADSCOMPONENTNAME: R_1005; ADSMODELNAME: s_CR10_000V; CDMASTERCADCELG: KC0005; CHIPSIZE: 1608; COMP: PRT_8; COMPONENTNAME: R_R.Normal_package; FNLEADFREETHET1GT2GMCTH1: N_N_N; FUNCTION: R_R.Normal_package; GCOUNT: 1; ICX_PART_MODEL: RES_0; INSTANCENAME: INS10594; MAKER: KOA; MAXGCOUNT: 1; MOUNTINGFORMSMD: SMD; NOTMOUNT: NOT MOUNT; OUMECLASSIFICATION: \ÊÀpÅèïRí; OUMEMAKER: HDK k¤dCHÆ; OUMEMAKERKATAMEI: CR10-000V; PARTNAME: Chip1608_GS_1; POWERRATING: 63m; QUADMODEL: RES_0; RESISTANCETOLER: X; SIZECODESMD: 1005; SQ_PART_MODEL: RES_0; VAL2: 100mW; VAL3: RK73Z1JTTD
R225 = R: ADSCNVFLAG: ON; ADSCOMPONENTNAME: R_1005; ADSMODELNAME: s_CR10_000V; CDMASTERCADCELG: KC0005; CHIPSIZE: 1608; COMP: PRT_8; COMPONENTNAME: R_R.Normal_package; FNLEADFREETHET1GT2GMCTH1: N_N_N; FUNCTION: R_R.Normal_package; GCOUNT: 1; ICX_PART_MODEL: RES_0; INSTANCENAME: INS10604; MAKER: KOA; MAXGCOUNT: 1; MOUNTINGFORMSMD: SMD; NOTMOUNT: NOT MOUNT; OUMECLASSIFICATION: \ÊÀpÅèïRí; OUMEMAKER: HDK k¤dCHÆ; OUMEMAKERKATAMEI: CR10-000V; PARTNAME: Chip1608_GS_1; POWERRATING: 63m; QUADMODEL: RES_0; RESISTANCETOLER: X; SIZECODESMD: 1005; SQ_PART_MODEL: RES_0; VAL2: 100mW; VAL3: RK73Z1JTTD
U?#1 = WAKU_DEF100: DATE: 2021-01-27; DRAWINGNUMBER: RD171-SCHEMATIC-01; FUNCTION: Photocoupler; REVISION: 01; SAVEAREA0: 168739,-66042,466246,90057; SAVECOUNT: 5; SHEETNUMBER: 7/8; TITLE: 1.6kW 48V Output Telecomunication / Equipment Power Supply; UPDATEDATE: 2021/01/27; UPDATETIME: 15:56:18
C59 = C: ADSCNVFLAG: ON; ADSCOMPONENTNAME: C_1005; ADSMODELNAME: s_UMK105BJ222KV_F; CAPACITANCETOLE: K; CDMASTERCADCELG: KC0005; CHIPSIZE: 1608; COMP: PRT_52; COMPONENTNAME: C_C.Normal_package; FNLEADFREETHET1GT2GMCTH1: 2_0_N; FUNCTION: C_C.Normal_package; GCOUNT: 1; ICX_PART_MODEL: CON_2.2N; INSTANCENAME: INS11769; MAKER: TDK; MAXGCOUNT: 1; NOMINALCAPACITA: 2.2n; OUMECLASSIFICATION: ƒZƒ‰ƒ~ƒbƒNƒRƒ“ƒfƒ“ƒT; OUMEMAKER: TYD ‘¾—z—U“d; OUMEMAKERKATAMEI: UMK105BJ222KV-F; PARTNAME: Chip1608_GS_1; PMPRODUCTSTYPEG: HD1-PC1; QUADMODEL: CON_2.2N; RATEDVOLTAGE: 50; SIZECODESMD: 1608; SQ_PART_MODEL: CON_2.2N; TEMPCHARACTERI2: B; VAL1: 1uF(K); VAL2: 50V
C92 = C: ADSMODELNAME: s_GRM155R71E104KE14D; CAPACITANCETOLE: K; CDMASTERCADCELG: KC0005; CHIPSIZE: 2012; COMP: PRT_52; COMPONENTNAME: C_C.Normal_package; FNLEADFREETHET1GT2GMCTH1: N_N_N; FUNCTION: C_C.Normal_package; GCOUNT: 1; INSTANCENAME: INS11789; MAKER: TDK; MAXGCOUNT: 1; NOMINALCAPACITA: 100n; OUMECLASSIFICATION: ƒZƒ‰ƒ~ƒbƒNƒRƒ“ƒfƒ“ƒT; OUMEMAKER: MRT ºc»ì; OUMEMAKERKATAMEI: GRM155R71E104KE14D; PARTNAME: Chip2012_GS_1; QUADMODEL: CON_100N; RATEDVOLTAGE: 25; SIZECODESMD: 2012; VAL1: 33nF(J); VAL2: 100V
C93 = C: ADSMODELNAME: s_GRM155R71E104KE14D; CAPACITANCETOLE: K; CDMASTERCADCELG: KC0005; CHIPSIZE: 1005; COMP: PRT_52; COMPONENTNAME: C_C.Normal_package; FNLEADFREETHET1GT2GMCTH1: N_N_N; FUNCTION: C_C.Normal_package; GCOUNT: 1; INSTANCENAME: INS11819; MAKER: TDK; MAXGCOUNT: 1; NOMINALCAPACITA: 100n; OUMECLASSIFICATION: ƒZƒ‰ƒ~ƒbƒNƒRƒ“ƒfƒ“ƒT; OUMEMAKER: MRT ºc»ì; OUMEMAKERKATAMEI: GRM155R71E104KE14D; PARTNAME: Chip2012_GS_1; QUADMODEL: CON_100N; RATEDVOLTAGE: 25; SIZECODESMD: 1005; VAL1: 33nF(J); VAL2: 100V
C94 = C: ADSMODELNAME: s_GRM155R71E104KE14D; CAPACITANCETOLE: K; CDMASTERCADCELG: KC0005; CHIPSIZE: 1005; COMP: PRT_52; COMPONENTNAME: C_C.Normal_package; FNLEADFREETHET1GT2GMCTH1: N_N_N; FUNCTION: C_C.Normal_package; GCOUNT: 1; INSTANCENAME: INS11799; MAKER: TDK; MAXGCOUNT: 1; NOMINALCAPACITA: 100n; OUMECLASSIFICATION: ƒZƒ‰ƒ~ƒbƒNƒRƒ“ƒfƒ“ƒT; OUMEMAKER: MRT ºc»ì; OUMEMAKERKATAMEI: GRM155R71E104KE14D; PARTNAME: Chip1005_GS_2; QUADMODEL: CON_100N; RATEDVOLTAGE: 25; SIZECODESMD: 1005; VAL1: 100nF(K); VAL2: 25V; VAL3: C1005X7R1E104K050BB
C100 = C: ADSMODELNAME: s_GRM155R71H222KA01D; CAPACITANCETOLE: K; CDMASTERCADCELG: KC0005; CHIPSIZE: 2012; COMP: PRT_52; COMPONENTNAME: C_C.Normal_package; FNLEADFREETHET1GT2GMCTH1: 2_0_N; FUNCTION: C_C.Normal_package; GCOUNT: 1; INSTANCENAME: INS11759; MAKER: TDK; MAXGCOUNT: 1; NOMINALCAPACITA: 2.2n; OUMECLASSIFICATION: ƒZƒ‰ƒ~ƒbƒNƒRƒ“ƒfƒ“ƒT; OUMEMAKER: MRT ºc»ì; OUMEMAKERKATAMEI: GRM155R71H222KA01D; PARTNAME: Chip2012_GS_1; PMPRODUCTSTYPEG: HD1; QUADMODEL: CON_2.2N; RATEDVOLTAGE: 50; SIZECODESMD: 2012; VAL1: 33nF(J); VAL2: 100V
C800 = CP: CAPACITANCETOLE: M; CDMASTERCADCELG: DC213N; CHIPSIZE: D35xL30; COMP: PRT_4; COMPONENTNAME: CP_CP.Normal_package; FNLEADFREETHET1GT2GMCTH1: 9_N_N; FUNCTION: CP_CP.Normal_package; GCOUNT: 1; INSTANCENAME: INS16773428; MAKER: RUBYCON; MAXGCOUNT: 1; NOMINALCAPACITA: 330u; OUMECLASSIFICATION: ƒAƒ‹ƒ~“d‰ðƒRƒ“ƒfƒ“ƒT; OUMEMAKER: SIT ƒ‹ƒrƒRƒ“; OUMEMAKERKATAMEI: 450MXC330M35X40; OUMEPARTTYPE: C; PARTNAME: EKXJ451E**6R8MJ16S_CC_2; QUADMODEL: CON_330U; RATEDVOLTAGE: 450; SIZECODESMD: DIP; VAL1: 6.8uF(M); VAL2: 450V; VAL3: 450MXH330
C801 = C: COMPONENTNAME: C_C; CURRENT: CIMAX; DIST: FLAT; INSTANCENAME: INS14557556; KNEE: CBMAX; MAX_TEMP: CTMAX; PARTNAME: Chip3216_GS_1; PIN NAMES ROTATE: False; PIN NUMBERS VISIBLE: False; PSPICETEMPLATE: C^@REFDES %1 %2 ?TOLERANCE|C^@REFDES| @VALUE ?IC/IC=@IC/ TC=@TC1,@TC2 ?TOLERANCE|\n.model C^@REFDES CAP C=1 DEV=@TOLERANCE%|; SLOPE: CSMAX; TC1: 0; TC2: 0; TIME: 16:40:05; UPDATETIME: 16:40:05; VAL1: 22nF(K); VAL2: 630V; VOLTAGE: CMAX
C802 = C: COMPONENTNAME: C_C; CURRENT: CIMAX; DIST: FLAT; INSTANCENAME: INS14557786; KNEE: CBMAX; MAX_TEMP: CTMAX; PARTNAME: Chip2012_GS_1; PIN NAMES ROTATE: False; PIN NUMBERS VISIBLE: False; PSPICETEMPLATE: C^@REFDES %1 %2 ?TOLERANCE|C^@REFDES| @VALUE ?IC/IC=@IC/ TC=@TC1,@TC2 ?TOLERANCE|\n.model C^@REFDES CAP C=1 DEV=@TOLERANCE%|; SLOPE: CSMAX; TC1: 0; TC2: 0; TIME: 16:40:05; UPDATETIME: 16:40:05; VAL1: 1.5uF(K); VAL2: 50V; VOLTAGE: CMAX
C803 = C: ADSMODELNAME: s_UMK105BJ272KV_F; CAPACITANCETOLE: K; CDMASTERCADCELG: DC834K; CHIPSIZE: 1005; COMP: PRT_52; COMPONENTNAME: C_C.Normal_package; FNLEADFREETHET1GT2GMCTH1: 3_0_N; FUNCTION: C_C.Normal_package; GCOUNT: 1; INSTANCENAME: INS14566383; MAKER: TDK; MAXGCOUNT: 1; NOMINALCAPACITA: 2.7n; NOTMOUNT: NOT MOUNT; OUMECLASSIFICATION: ƒZƒ‰ƒ~ƒbƒNƒRƒ“ƒfƒ“ƒT; OUMEMAKER: TYD ‘¾—z—U“d; OUMEMAKERKATAMEI: UMK105BJ272KV-F; PARTNAME: Chip1608_GS_1; PMPRODUCTSTYPEG: PC1; QUADMODEL: CON_2.7N; RATEDVOLTAGE: 50; SIZECODESMD: 1005; TEMPCHARACTERI2: B; VAL1: 2700 pF(K); VAL2: 50V; VAL3: UMK105BJ272KV-F
C804 = CP: CAPACITANCETOLE: M; CDMASTERCADCELG: DC213N; CHIPSIZE: D35xL30; COMP: PRT_4; COMPONENTNAME: CP_CP.Normal_package; FNLEADFREETHET1GT2GMCTH1: 9_N_N; FUNCTION: CP_CP.Normal_package; GCOUNT: 1; INSTANCENAME: INS16773861; MAKER: RUBYCON; MAXGCOUNT: 1; NOMINALCAPACITA: 330u; OUMECLASSIFICATION: ƒAƒ‹ƒ~“d‰ðƒRƒ“ƒfƒ“ƒT; OUMEMAKER: SIT ƒ‹ƒrƒRƒ“; OUMEMAKERKATAMEI: 450MXC330M35X40; OUMEPARTTYPE: C; PARTNAME: EKZH350E**331MJC5S_CC_3; QUADMODEL: CON_330U; RATEDVOLTAGE: 450; SIZECODESMD: DIP; VAL1: 330uF(M); VAL2: 35V; VAL3: 450MXH330
C805 = C: COMPONENTNAME: C_C; CURRENT: CIMAX; DIST: FLAT; IC: 0; INSTANCENAME: INS16769854; KNEE: CBMAX; MAX_TEMP: CTMAX; PARTNAME: Chip1005_GS_2; PIN NAMES ROTATE: False; PIN NUMBERS VISIBLE: False; PSPICETEMPLATE: C^@REFDES %1 %2 ?TOLERANCE|C^@REFDES| @VALUE ?IC/IC=@IC/ ?TOLERANCE|\n.model C^@REFDES CAP C=1 DEV=@TOLERANCE%|; SLOPE: CSMAX; TIME: 16:40:05; UPDATETIME: 16:40:05; VAL1: 1nF(K); VAL2: 50V; VOLTAGE: CMAX
C806 = C#1: COMPONENTNAME: C_C; CURRENT: CIMAX; CaptureCellPackProp: C##1; DIST: FLAT; INSTANCENAME: INS16769768; KNEE: CBMAX; MAX_TEMP: CTMAX; PARTNAME: Chip3216_GS_1; PIN NAMES ROTATE: False; PIN NUMBERS VISIBLE: False; PSPICETEMPLATE: C^@REFDES %1 %2 ?TOLERANCE|C^@REFDES| @VALUE ?IC/IC=@IC/ ?TOLERANCE|\n.model C^@REFDES CAP C=1 DEV=@TOLERANCE%|; SLOPE: CSMAX; TIME: 16:40:05; UPDATETIME: 16:40:05; VAL1: 10uF(K); VAL2: 25V; VOLTAGE: CMAX
C807 = C: COMPONENTNAME: C_C; CURRENT: CIMAX; DIST: FLAT; INSTANCENAME: INS16790223; KNEE: CBMAX; MAX_TEMP: CTMAX; PARTNAME: Chip3216_GS_1; PIN NAMES ROTATE: False; PIN NUMBERS VISIBLE: False; PSPICETEMPLATE: C^@REFDES %1 %2 ?TOLERANCE|C^@REFDES| @VALUE ?IC/IC=@IC/ TC=@TC1,@TC2 ?TOLERANCE|\n.model C^@REFDES CAP C=1 DEV=@TOLERANCE%|; SLOPE: CSMAX; TC1: 0; TC2: 0; TIME: 16:40:05; UPDATETIME: 16:40:05; VAL1: 22nF(K); VAL2: 630V; VOLTAGE: CMAX
C808 = C#1: COMPONENTNAME: C_C; CURRENT: CIMAX; CaptureCellPackProp: C##1; DIST: FLAT; INSTANCENAME: INS16769784; KNEE: CBMAX; MAX_TEMP: CTMAX; NOTMOUNT: NOT MOUNT; PARTNAME: Chip1005_GS_2; PIN NAMES ROTATE: False; PIN NUMBERS VISIBLE: False; PSPICETEMPLATE: C^@REFDES %1 %2 ?TOLERANCE|C^@REFDES| @VALUE ?IC/IC=@IC/ ?TOLERANCE|\n.model C^@REFDES CAP C=1 DEV=@TOLERANCE%|; SLOPE: CSMAX; TIME: 16:40:05; UPDATETIME: 16:40:05; VAL1: 2.2nF(K); VAL2: 50V; VOLTAGE: CMAX
C809 = CP: CAPACITANCETOLE: M; CDMASTERCADCELG: DC213N; CHIPSIZE: D8xL20; COMP: PRT_4; COMPONENTNAME: CP_CP.Normal_package; FNLEADFREETHET1GT2GMCTH1: 9_N_N; FUNCTION: CP_CP.Normal_package; GCOUNT: 1; INSTANCENAME: INS16773655; MAKER: NIPPON CHEMI-CON; MAXGCOUNT: 1; NOMINALCAPACITA: 1000u; OUMECLASSIFICATION: ƒAƒ‹ƒ~“d‰ðƒRƒ“ƒfƒ“ƒT; OUMEMAKER: SIT ƒ‹ƒrƒRƒ“; OUMEPARTTYPE: C; PARTNAME: EKZH160E**102MH20D_CC_1; QUADMODEL: CON_330U; RATEDVOLTAGE: 16; SIZECODESMD: DIP; VAL1: 1000uF(M); VAL2: 16V
C810 = C: COMPONENTNAME: C_C; CURRENT: CIMAX; DIST: FLAT; INSTANCENAME: INS16790089; KNEE: CBMAX; MAX_TEMP: CTMAX; PARTNAME: Chip1005_GS_2; PIN NAMES ROTATE: False; PIN NUMBERS VISIBLE: False; PSPICETEMPLATE: C^@REFDES %1 %2 ?TOLERANCE|C^@REFDES| @VALUE ?IC/IC=@IC/ TC=@TC1,@TC2 ?TOLERANCE|\n.model C^@REFDES CAP C=1 DEV=@TOLERANCE%|; SLOPE: CSMAX; TC1: 0; TC2: 0; TIME: 16:40:05; UPDATETIME: 16:40:05; VAL1: 470pF(J); VAL2: 50V; VOLTAGE: CMAX
C811 = C: ADSMODELNAME: s_DE2B3SA471KN3AT02F; CAPACITANCETOLE: K; CDMASTERCADCELG: RD0002; COMP: PRT_50; COMPONENTNAME: C_C.Normal_package; FNLEADFREETHET1GT2GMCTH1: 9_1_N; FUNCTION: C_C.Normal_package; GCOUNT: 1; INSTANCENAME: INS16997067; MAKER: MURATA; MAXGCOUNT: 1; NOMINALCAPACITA: 470p; OUMECLASSIFICATION: ƒZƒ‰ƒ~ƒbƒNƒRƒ“ƒfƒ“ƒT; OUMEMAKER: MRT ºc»ì; PARTNAME: DE1B3RA471_GS_1; QUADMODEL: CON_470P; RATEDVOLTAGE: 1K; SIZECODESMD: DIP; TEMPCHARACTERI2: B; VAL1: 470pF(K); VAL2: 250V; VAL3: DE1B3RA471KA4BN01F
C812 = C: ADSMODELNAME: s_UMK105BJ272KV_F; CAPACITANCETOLE: K; CDMASTERCADCELG: DC834K; CHIPSIZE: 1005; COMP: PRT_52; COMPONENTNAME: C_C.Normal_package; FNLEADFREETHET1GT2GMCTH1: 3_0_N; FUNCTION: C_C.Normal_package; GCOUNT: 1; INSTANCENAME: INS16997896; MAKER: TDK; MAXGCOUNT: 1; NOMINALCAPACITA: 2.7n; OUMECLASSIFICATION: ƒZƒ‰ƒ~ƒbƒNƒRƒ“ƒfƒ“ƒT; OUMEMAKER: TYD ‘¾—z—U“d; OUMEMAKERKATAMEI: UMK105BJ272KV-F; PARTNAME: Chip1005_GS_2; PMPRODUCTSTYPEG: PC1; QUADMODEL: CON_2.7N; RATEDVOLTAGE: 50; SIZECODESMD: 1005; TEMPCHARACTERI2: B; VAL1: 15pF(F); VAL2: 50V; VAL3: UMK105BJ272KV-F
CN6 = CN1_1: COMP: PRT_38; COMPONENTNAME: CN1_1_CN1_1.Normal_package; FUNCTION: CN1_1_CN1_1.Normal_package; INSTANCENAME: INS17073174; MAKER: OSADA; PARTNAME: OP-910_GS
CN7 = CN1_2: COMP: PRT_38; COMPONENTNAME: CN1_2_CN1_2.Normal_package; FUNCTION: CN1_2_CN1_2.Normal_package; INSTANCENAME: INS17073180; MAKER: OSADA; PARTNAME: OP-910_GS; VAL3: OP-910-F73
CN8 = CN2: COMP: PRT_42; COMPONENTNAME: CN2_CN2.Normal_package; FUNCTION: CN2_CN2.Normal_package; INSTANCENAME: INS11865; MAKER: MOLEX; PARTNAME: 5045-02A_MX
CN9 = CN2: COMP: PRT_42; COMPONENTNAME: CN2_CN2.Normal_package; FUNCTION: CN2_CN2.Normal_package; INSTANCENAME: INS17018717; MAKER: MOLEX; PARTNAME: 5045-02A_MX
D80 = D_D1_0: BIASVALUE POWER: 0W; COMPONENTNAME: D_D1_0_D_D1_0; INSTANCENAME: INS14557726; PARTNAME: CRF03_TS_A; USERCOMPTEXT3: TOSHIBA
D81 = D_D1_0: BIASVALUE POWER: 0W; COMPONENTNAME: D_D1_0_D_D1_0; INSTANCENAME: INS14550497; PARTNAME: 1SS403E_TS_B; USERCOMPTEXT3: TOSHIBA
D82 = D_D1_0: BIASVALUE POWER: 0W; COMPONENTNAME: D_D1_0_D_D1_0; INSTANCENAME: INS14565946; PARTNAME: CMH07_TS_B; USERCOMPTEXT3: TOSHIBA
D83 = D_D_1: BIASVALUE POWER: <BiasValue Power>; COMPONENTNAME: D_D_1_D_D_1; INSTANCENAME: INS16769596; PARTNAME: CRS01_TS_B; USERCOMPTEXT3: TOSHIBA
D84 = DMH: COMP: PRT_25; COMPONENTNAME: DMH_DMH.Normal_package; FUNCTION: DMH_DMH.Normal_package; INSTANCENAME: INS16774725; MAKER: TOSHIBA; NOTMOUNT: NOT MOUNT; PARTNAME: TBAT54_TS_B; USERCOMPTEXT3: TOSHIBA
D90 = D_D1_0: BIASVALUE POWER: 0W; COMPONENTNAME: D_D1_0_D_D1_0; INSTANCENAME: INS687401; PARTNAME: CMH07_TS_B; USERCOMPTEXT3: TOSHIBA
D91 = D_D1_0: BIASVALUE POWER: 0W; COMPONENTNAME: D_D1_0_D_D1_0; INSTANCENAME: INS16791338; PARTNAME: CMH07_TS_B; USERCOMPTEXT3: TOSHIBA
D92 = D_D1_0: BIASVALUE POWER: 0W; COMPONENTNAME: D_D1_0_D_D1_0; INSTANCENAME: INS16791357; PARTNAME: CMH07_TS_B; USERCOMPTEXT3: TOSHIBA
F8 = F: COMP: PRT_21; COMPONENTNAME: F_F.Normal_package; FUNCTION: F_F.Normal_package; GCOUNT: 1; INSTANCENAME: INS16774494; MAKER: Littelfuse; MAXGCOUNT: 1; MOUNTINGFORMSMD: SMD; NOMINALOPERATIO: 0; PARTNAME: 808****0440_LF; RATEDINTERRUPTI: 0; RATEDVOLTAGE: 0
IC8 = L2412_0: COMP: PRT_62; COMPONENTNAME: L2412_0_L2412_0; INSTANCENAME: INS11539; MAKER: TEXAS; PARTNAME: LM74700-Q1_TI; SAVECOUNT: 1; UPDATEDATE: 2020/07/08; UPDATETIME: 16:40:05
IC80 = UCC28710_0: BIASVALUE POWER: 0W; COMPONENTNAME: UCC28710_0_UCC28710_0; INSTANCENAME: INS14550599; PARTNAME: UCC28711D_TI; SAVECOUNT: 1; UPDATEDATE: 2020/07/08; UPDATETIME: 16:40:05
IC81 = LM317_TRANS_0: BIASVALUE POWER: <BiasValue Power>; COMPONENTNAME: LM317_TRANS_0_LM317_TRANS_0.Normal_package; FUNCTION: LM317_TRANS_0_LM317_TRANS_0.Normal_package; INSTANCENAME: INS16769638; PARTNAME: LM317MDCY_TI; POWER: <BiasValue Power>
Q15 = MFNAC: COMP: PRT_60; COMPONENTNAME: MFNAC_MFNAC.Normal_package; FUNCTION: MFNAC_MFNAC.Normal_package; INSTANCENAME: INS11627; MAKER: TOSHIBA; PARTNAME: TPH2R408QM_TS; USERCOMPTEXT3: TOSHIBA
Q16 = MFNAC: COMP: PRT_60; COMPONENTNAME: MFNAC_MFNAC.Normal_package; FUNCTION: MFNAC_MFNAC.Normal_package; INSTANCENAME: INS11649; MAKER: TOSHIBA; PARTNAME: TPH2R408QM_TS; USERCOMPTEXT3: TOSHIBA
Q17 = MFNAC: COMP: PRT_60; COMPONENTNAME: MFNAC_MFNAC.Normal_package; FUNCTION: MFNAC_MFNAC.Normal_package; INSTANCENAME: INS11583; MAKER: TOSHIBA; PARTNAME: TPH2R408QM_TS; USERCOMPTEXT3: TOSHIBA
Q18 = MFNAC: COMP: PRT_60; COMPONENTNAME: MFNAC_MFNAC.Normal_package; FUNCTION: MFNAC_MFNAC.Normal_package; INSTANCENAME: INS11605; MAKER: TOSHIBA; PARTNAME: TPH2R408QM_TS; USERCOMPTEXT3: TOSHIBA
Q80 = MFNF_0: COMP: PRT_9; COMPONENTNAME: MFNF_0_MFNF_0; INSTANCENAME: INS66344; MAKER: TOSHIBA; PARTNAME: TK12A80W_TS_1; USERCOMPTEXT3: TOSHIBA
R6 = R: ADSMODELNAME: s_RC0603JR_072R2L; CDMASTERCADCELG: KC0008; CHIPSIZE: 1608; COMP: PRT_8; COMPONENTNAME: R_R.Normal_package; FNLEADFREETHET1GT2GMCTH1: 2_1_N; FUNCTION: R_R.Normal_package; GCOUNT: 1; INSTANCENAME: INS11779; MAKER: KAMAYA; MAXGCOUNT: 1; MOUNTINGFORMSMD: SMD; OUMECLASSIFICATION: \ÊÀpÅèïRí; OUMEMAKER: YGO ƒ„ƒQƒI; OUMEMAKERKATAMEI: RC0603JR-072R2L; PARTNAME: Chip1608_GS_1; PMPRODUCTSTYPEG: PC1; POWERRATING: 100m; QUADMODEL: RES_2.2; RESISTANCETOLER: J; SIZECODESMD: 1608; VAL1: 2.2(J); VAL2: 100mW; VAL3: RMC1/16 - 2R2J TP
R204 = R: ADSMODELNAME: s_RK73Z1JTTD; CDMASTERCADCELG: KCK0203; CHIPSIZE: 1608; COMP: PRT_8; COMPONENTNAME: R_R.Normal_package; FNLEADFREETHET1GT2GMCTH1: 3_2_N; FUNCTION: R_R.Normal_package; GCOUNT: 1; INSTANCENAME: INS11829; MAKER: KOA; MAXGCOUNT: 1; MOUNTINGFORMSMD: SMD; OUMECLASSIFICATION: \ÊÀpÅèïRí; OUMEMAKER: KOA R[A; OUMEMAKERKATAMEI: RK73Z1JTTD; PARTNAME: Chip1608_GS_1; PMPRODUCTSTYPEG: DME-HD1-PC1; POWERRATING: 100m; QUADMODEL: RES_0; RESISTANCETOLER: X; SIZECODESMD: 1608; VAL2: 100mW; VAL3: RK73Z1JTTD
R205 = R: ADSMODELNAME: s_RK73Z1JTTD; CDMASTERCADCELG: KCK0203; CHIPSIZE: 1608; COMP: PRT_8; COMPONENTNAME: R_R.Normal_package; FNLEADFREETHET1GT2GMCTH1: 3_2_N; FUNCTION: R_R.Normal_package; GCOUNT: 1; INSTANCENAME: INS11809; MAKER: KOA; MAXGCOUNT: 1; MOUNTINGFORMSMD: SMD; OUMECLASSIFICATION: \ÊÀpÅèïRí; OUMEMAKER: KOA R[A; OUMEMAKERKATAMEI: RK73Z1JTTD; PARTNAME: Chip1608_GS_1; PMPRODUCTSTYPEG: DME-HD1-PC1; POWERRATING: 100m; QUADMODEL: RES_0; RESISTANCETOLER: X; SIZECODESMD: 1608; VAL2: 100mW; VAL3: RK73Z1JTTD
R206 = R: ADSMODELNAME: s_RK73Z1JTTD; CDMASTERCADCELG: KCK0203; CHIPSIZE: 1608; COMP: PRT_8; COMPONENTNAME: R_R.Normal_package; FNLEADFREETHET1GT2GMCTH1: 3_2_N; FUNCTION: R_R.Normal_package; GCOUNT: 1; INSTANCENAME: INS11839; MAKER: KOA; MAXGCOUNT: 1; MOUNTINGFORMSMD: SMD; OUMECLASSIFICATION: \ÊÀpÅèïRí; OUMEMAKER: KOA R[A; OUMEMAKERKATAMEI: RK73Z1JTTD; PARTNAME: Chip1608_GS_1; PMPRODUCTSTYPEG: DME-HD1-PC1; POWERRATING: 100m; QUADMODEL: RES_0; RESISTANCETOLER: X; SIZECODESMD: 1608; VAL2: 100mW; VAL3: RK73Z1JTTD
R800 = R: BIASVALUE POWER: 0W; COMPONENTNAME: R_R; DIST: FLAT; INSTANCENAME: INS14550461; MAX_TEMP: RTMAX; PARTNAME: MOS3C_KO; PIN NAMES ROTATE: False; PIN NUMBERS VISIBLE: False; POWER: RMAX; PSPICETEMPLATE: R^@REFDES %1 %2 ?TOLERANCE|R^@REFDES| @VALUE TC=@TC1,@TC2 ?TOLERANCE|\n.model R^@REFDES RES R=1 DEV=@TOLERANCE%|; SLOPE: RSMAX; TC1: 0; TC2: 0; TIME: 16:40:05; UPDATETIME: 16:40:05; VAL1: 27k(J); VAL2: 3w; VOLTAGE: RVMAX
R801 = R: ADSMODELNAME: s_RC0603JR_072R2L; CDMASTERCADCELG: KC0008; CHIPSIZE: 1608; COMP: PRT_8; COMPONENTNAME: R_R.Normal_package; FNLEADFREETHET1GT2GMCTH1: 2_1_N; FUNCTION: R_R.Normal_package; GCOUNT: 1; INSTANCENAME: INS16790038; MAKER: KAMAYA; MAXGCOUNT: 1; MOUNTINGFORMSMD: SMD; NOMINALRESISTAN: 2.2; OUMECLASSIFICATION: \ÊÀpÅèïRí; OUMEMAKER: YGO ƒ„ƒQƒI; OUMEMAKERKATAMEI: RC0603JR-072R2L; PARTNAME: Chip3225_GS_1; PMPRODUCTSTYPEG: PC1; POWERRATING: 100m; QUADMODEL: RES_2.2; RESISTANCETOLER: J; SIZECODESMD: 1608; VAL1: 33(J); VAL2: 100mW,}5%; VAL3: RMC1/16 - 2R2J TP
R802 = R: ADSMODELNAME: s_RC0603JR_072R2L; CDMASTERCADCELG: KC0008; CHIPSIZE: 1608; COMP: PRT_8; COMPONENTNAME: R_R.Normal_package; FNLEADFREETHET1GT2GMCTH1: 2_1_N; FUNCTION: R_R.Normal_package; GCOUNT: 1; INSTANCENAME: INS14565241; MAKER: KAMAYA; MAXGCOUNT: 1; MOUNTINGFORMSMD: SMD; NOMINALRESISTAN: 2.2; OUMECLASSIFICATION: \ÊÀpÅèïRí; OUMEMAKER: YGO ƒ„ƒQƒI; OUMEMAKERKATAMEI: RC0603JR-072R2L; PARTNAME: Chip3216_GS_1; PMPRODUCTSTYPEG: PC1; POWERRATING: 100m; QUADMODEL: RES_2.2; RESISTANCETOLER: J; SIZECODESMD: 1608; VAL1: 10(J); VAL2: 100mW,}5%; VAL3: RMC1/16 - 2R2J TP
R803 = R: BIASVALUE POWER: 0W; COMPONENTNAME: R_R; DIST: FLAT; INSTANCENAME: INS14552964; MAX_TEMP: RTMAX; PARTNAME: Chip1608_GS_1; PIN NAMES ROTATE: False; PIN NUMBERS VISIBLE: False; POWER: RMAX; PSPICETEMPLATE: R^@REFDES %1 %2 ?TOLERANCE|R^@REFDES| @VALUE TC=@TC1,@TC2 ?TOLERANCE|\n.model R^@REFDES RES R=1 DEV=@TOLERANCE%|; SLOPE: RSMAX; TC1: 0; TC2: 0; TIME: 16:40:05; UPDATETIME: 16:40:05; VAL1: 10k(J); VOLTAGE: RVMAX
R804 = R: ADSMODELNAME: s_RK73B1JTTD272J@@; CDMASTERCADCELG: KC0133; CHIPSIZE: 1608; COMP: PRT_8; COMPONENTNAME: R_R.Normal_package; FNLEADFREETHET1GT2GMCTH1: N_N_N; FUNCTION: R_R.Normal_package; GCOUNT: 1; INSTANCENAME: INS14565500; MAKER: KOA; MAXGCOUNT: 1; MOUNTINGFORMSMD: SMD; NOMINALRESISTAN: 2.7K; OUMECLASSIFICATION: \ÊÀpÅèïRí; OUMEMAKER: KOA R[A; OUMEMAKERKATAMEI: RK73B1JTTD272J@@; PARTNAME: Chip1608_GS_1; POWERRATING: 100m; QUADMODEL: RES_10K; RESISTANCETOLER: J; SIZECODESMD: 1608; VAL1: 2.7K(J); VAL2: 100mW,}5%; VAL3: RK73B1JTTD272J
R806 = R: BIASVALUE POWER: 0W; COMPONENTNAME: R_R; DIST: FLAT; INSTANCENAME: INS14550549; MAX_TEMP: RTMAX; PARTNAME: Chip3216_GS_1; PIN NAMES ROTATE: False; PIN NUMBERS VISIBLE: False; POWER: RMAX; PSPICETEMPLATE: R^@REFDES %1 %2 ?TOLERANCE|R^@REFDES| @VALUE TC=@TC1,@TC2 ?TOLERANCE|\n.model R^@REFDES RES R=1 DEV=@TOLERANCE%|; SLOPE: RSMAX; TC1: 0; TC2: 0; TIME: 16:40:05; UPDATETIME: 16:40:05; VAL1: 22(J); VOLTAGE: RVMAX
R807 = R: BIASVALUE POWER: 0W; COMPONENTNAME: R_R; DIST: FLAT; INSTANCENAME: INS14550861; MAX_TEMP: RTMAX; PARTNAME: Chip1608_GS_1; PIN NAMES ROTATE: False; PIN NUMBERS VISIBLE: False; POWER: RMAX; PSPICETEMPLATE: R^@REFDES %1 %2 ?TOLERANCE|R^@REFDES| @VALUE TC=@TC1,@TC2 ?TOLERANCE|\n.model R^@REFDES RES R=1 DEV=@TOLERANCE%|; SLOPE: RSMAX; TC1: 0; TC2: 0; TIME: 16:40:05; UPDATETIME: 16:40:05; VAL1: 100k(J); VOLTAGE: RVMAX
R808 = R: BIASVALUE POWER: 0W; COMPONENTNAME: R_R; DIST: FLAT; INSTANCENAME: INS14550571; MAX_TEMP: RTMAX; PARTNAME: Chip1608_GS_1; PIN NAMES ROTATE: False; PIN NUMBERS VISIBLE: False; POWER: RMAX; PSPICETEMPLATE: R^@REFDES %1 %2 ?TOLERANCE|R^@REFDES| @VALUE TC=@TC1,@TC2 ?TOLERANCE|\n.model R^@REFDES RES R=1 DEV=@TOLERANCE%|; SLOPE: RSMAX; TC1: 0; TC2: 0; TIME: 16:40:05; UPDATETIME: 16:40:05; VAL1: 110k(F); VOLTAGE: RVMAX
R809 = R: BIASVALUE POWER: 0W; COMPONENTNAME: R_R; DIST: FLAT; INSTANCENAME: INS14550671; MAX_TEMP: RTMAX; PARTNAME: Chip1608_GS_1; PIN NAMES ROTATE: False; PIN NUMBERS VISIBLE: False; POWER: RMAX; PSPICETEMPLATE: R^@REFDES %1 %2 ?TOLERANCE|R^@REFDES| @VALUE TC=@TC1,@TC2 ?TOLERANCE|\n.model R^@REFDES RES R=1 DEV=@TOLERANCE%|; SLOPE: RSMAX; TC1: 0; TC2: 0; TIME: 16:40:05; UPDATETIME: 16:40:05; VAL1: 27k(F); VOLTAGE: RVMAX
R810 = R: COMPONENTNAME: R_R; DIST: FLAT; INSTANCENAME: INS16769736; MAX_TEMP: RTMAX; PARTNAME: Chip1608_GS_1; PIN NAMES ROTATE: False; PIN NUMBERS VISIBLE: False; POWER: RMAX; PSPICETEMPLATE: R^@REFDES %1 %2 ?TOLERANCE|R^@REFDES| @VALUE TC=@TC1,@TC2 ?TOLERANCE|\n.model R^@REFDES RES R=1 DEV=@TOLERANCE%|; SLOPE: RSMAX; TC1: 0; TC2: 0; TIME: 16:40:05; UPDATETIME: 16:40:05; VAL1: 270(F); VOLTAGE: RVMAX
R811 = R: COMPONENTNAME: R_R; DIST: FLAT; INSTANCENAME: INS16769832; MAX_TEMP: RTMAX; PARTNAME: Chip1608_GS_1; PIN NAMES ROTATE: False; PIN NUMBERS VISIBLE: False; POWER: RMAX; PSPICETEMPLATE: R^@REFDES %1 %2 ?TOLERANCE|R^@REFDES| @VALUE TC=@TC1,@TC2 ?TOLERANCE|\n.model R^@REFDES RES R=1 DEV=@TOLERANCE%|; SLOPE: RSMAX; TC1: 0; TC2: 0; TIME: 16:40:05; UPDATETIME: 16:40:05; VAL1: 2.37k(F); VOLTAGE: RVMAX
R812 = R: ADSMODELNAME: s_ERJ8GEYJ3R3V; CDMASTERCADCELG: KC0014; CHIPSIZE: 3216; COMP: PRT_5; COMPONENTNAME: R_R.Normal_package; FNLEADFREETHET1GT2GMCTH1: N_N_N; FUNCTION: R_R.Normal_package; GCOUNT: 1; INSTANCENAME: INS16790614; MAKER: VISHAY; MAXGCOUNT: 1; MOUNTINGFORMSMD: SMD; NOMINALRESISTAN: 3.3; OUMECLASSIFICATION: \ÊÀpÅèïRí; OUMEMAKER: NAE pi\jbNGNgjbNfoCX; OUMEMAKERKATAMEI: ERJ8GEYJ3R3V; PARTNAME: Chip3216_GS_1; POWERRATING: 250m; QUADMODEL: RES_3.3; RESISTANCETOLER: J; SIZECODESMD: 3216; VAL1: 1.1(F); VAL2: 500mW,}1%; VAL3: CRCW12063R01FKEAHP
R813 = R: ADSMODELNAME: s_ERJ8GEYJ3R3V; CDMASTERCADCELG: KC0014; CHIPSIZE: 3216; COMP: PRT_5; COMPONENTNAME: R_R.Normal_package; FNLEADFREETHET1GT2GMCTH1: N_N_N; FUNCTION: R_R.Normal_package; GCOUNT: 1; INSTANCENAME: INS14565352; MAKER: VISHAY; MAXGCOUNT: 1; MOUNTINGFORMSMD: SMD; NOMINALRESISTAN: 3.3; OUMECLASSIFICATION: \ÊÀpÅèïRí; OUMEMAKER: NAE pi\jbNGNgjbNfoCX; OUMEMAKERKATAMEI: ERJ8GEYJ3R3V; PARTNAME: Chip3216_GS_1; POWERRATING: 250m; QUADMODEL: RES_3.3; RESISTANCETOLER: J; SIZECODESMD: 3216; VAL1: 1.1(F); VAL2: 500mW,}1%; VAL3: CRCW12063R01FKEAHP
R814 = R: ADSMODELNAME: s_RK73H2BTTD1R50F; CDMASTERCADCELG: KC0014; CHIPSIZE: 3216; COMP: PRT_5; COMPONENTNAME: R_R.Normal_package; FNLEADFREETHET1GT2GMCTH1: N_N_N; FUNCTION: R_R.Normal_package; GCOUNT: 1; INSTANCENAME: INS16790603; MAKER: KOA; MAXGCOUNT: 1; MOUNTINGFORMSMD: SMD; NOMINALRESISTAN: 3.3; OUMECLASSIFICATION: \ÊÀpÅèïRí; OUMEMAKER: KOA; PARTNAME: Chip3216_GS_1; POWERRATING: 250m; QUADMODEL: RES_3.3; RESISTANCETOLER: J; SIZECODESMD: 3216; VAL1: 1.5(F); VAL2: 250mW,}1%
R820 = R: BIASVALUE POWER: 0W; COMPONENTNAME: R_R; DIST: FLAT; INSTANCENAME: INS687465; MAX_TEMP: RTMAX; PARTNAME: Chip3216_GS_1; PIN NAMES ROTATE: False; PIN NUMBERS VISIBLE: False; POWER: RMAX; PSPICETEMPLATE: R^@REFDES %1 %2 ?TOLERANCE|R^@REFDES| @VALUE TC=@TC1,@TC2 ?TOLERANCE|\n.model R^@REFDES RES R=1 DEV=@TOLERANCE%|; SLOPE: RSMAX; TC1: 0; TC2: 0; TIME: 16:40:05; UPDATETIME: 16:40:05; VAL1: 1.2k(J); VAL2: 250mW; VOLTAGE: RVMAX
T8 = T3_14: PARTNAME: WT2020_GS; VAL1: 36:08:05; VAL3: WT2020B
TP28 = TP: COMP: PRT_44; COMPONENTNAME: TP_TP.Normal_package; FUNCTION: TP_TP.Normal_package; INSTANCENAME: INS11849; MAKER: MAC8; PARTNAME: HK-2_M8
TP31 = TP: COMP: PRT_44; COMPONENTNAME: TP_TP.Normal_package; FUNCTION: TP_TP.Normal_package; INSTANCENAME: INS11857; MAKER: MAC8; PARTNAME: HK-2_M8
TP80 = TP: COMP: PRT_44; COMPONENTNAME: TP_TP.Normal_package; FUNCTION: TP_TP.Normal_package; INSTANCENAME: INS16775798; MAKER: MAC8; PARTNAME: HK-2_M8
TP81 = TP: COMP: PRT_44; COMPONENTNAME: TP_TP.Normal_package; FUNCTION: TP_TP.Normal_package; INSTANCENAME: INS16775838; MAKER: MAC8; PARTNAME: HK-2_M8
TP82 = TP: COMP: PRT_44; COMPONENTNAME: TP_TP.Normal_package; FUNCTION: TP_TP.Normal_package; INSTANCENAME: INS16775922; MAKER: MAC8; PARTNAME: HK-2_M8
U?#8 = WAKU_DEF100: DATE: 2021-01-27; DRAWINGNUMBER: RD171-SCHEMATIC-01; FUNCTION: ORing & 48VOutput & Control Power; REVISION: 01; SAVEAREA0: 168739,-66042,466246,90057; SAVECOUNT: 5; SHEETNUMBER: 8/8; TITLE: 1.6kW 48V Output Telecomunication / Equipment Power Supply; UPDATEDATE: 2021/01/27; UPDATETIME: 15:56:18

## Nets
P48V: C92.2 C93.2 C100.2 CN6.1 CN6.2 IC8.4(6) Q15.5 Q15.6 Q15.7 Q15.8 Q16.5 Q16.6 Q16.7 Q16.8 Q17.5 Q17.6 Q17.7 Q17.8 Q18.5 Q18.6 Q18.7 Q18.8
VCC3R3_1: C95.2 C96.2 C97.2 C98.2 IC21.5 IC22.5 IC23.5 IC24.5 R157.1 R160.1 R163.1 R166.1 R186.2 R188.2 R190.2 R192.2 ; also on sheet 6
VCC12R0_1: C806.1(2) D83.A D84.C IC81.OUT_0 IC81.OUT_1 R810.1 TP82.1 ; also on sheet 5 6 7 8
VCC12R0_2: C809.2 CN8.1 CN9.1 D90.C D91.C D92.C R820.2 TP81.1 ; also on sheet 3 4
ADJ: C805.1 D84.A IC81.ADJ R810.2 R811.1
Aux: C810.2 D81.A R808.2 T8.6
CONN004: C59.2 IC8.3(2) IC8.6(7) Q15.1 Q15.2 Q15.3 Q16.1 Q16.2 Q16.3 Q17.1 Q17.2 Q17.3 Q18.1 Q18.2 Q18.3 TP31.1 ; also on sheet 3 4
FG6: C93.1 C94.2 R205.1 R206.1
FG7: R204.1
HS1_1: R224.2
HS1_2: R225.2
IN: C804.2 C808.1(2) D82.C D83.C IC81.IN
LGND: C92.1 C94.1 C100.1 C809.1 C811.1 CN7.1 CN7.2 CN8.2 CN9.2 IC8.2(4) R194.2 R195.2 R196.2 R197.2 R204.2 R205.2 R206.2 R820.1 T8.8(5) T8.9(3) ; also on sheet 3 4 5 8
OUTA1: IC21.4 R187.2 ; also on sheet 5
OUTA2: R149.2 ; also on sheet 3
OUTB1: IC22.4 R189.2 ; also on sheet 5
OUTB2: R150.2 ; also on sheet 3
OUTC1: IC23.4 R191.2 ; also on sheet 5
OUTC2: R151.2 ; also on sheet 3
OUTD1: IC24.4 R193.2 ; also on sheet 5
OUTD2: R152.2 ; also on sheet 3
PFC_OUT: F8.1 ; also on sheet 5 6 7
PN: C71.1 C72.1 C73.1 C74.1 C95.1 C96.1 C97.1 C98.1 C800.1 C802.1 C803.1 C804.1 C805.2 C806.2(1) C808.2(1) C811.2 C812.1 HS5.1 HS6.1 IC13.4 IC14.4 IC15.4 IC16.4 IC21.3 IC22.3 IC23.3 IC24.3 IC80.GND R187.1 R189.1 R191.1 R193.1 R220.1 R221.1 R222.1 R223.1 R224.1 R225.1 R801.2 R807.1 R809.1 R811.2 R812.1 R813.1 R814.1 T8.4(6) ; also on sheet 5 6 7 8
SIG13: D81.C R806.1
SIG136: IC8.5 R6.1
SIG228: IC13.5 R153.2
SIG229: C71.2 IC13.6 R157.2
SIG230: IC13.1 R149.1
SIG231: C72.2 IC14.6 R160.2
SIG234: IC14.5 R154.2
SIG236: IC14.1 R150.1
SIG237: C73.2 IC15.6 R163.2
SIG242: IC15.5 R155.2
SIG243: IC16.1 R152.1
SIG245: IC16.5 R156.2
SIG246: C74.2 IC16.6 R166.2
SIG247: IC15.1 R151.1
SIG555: C59.1 IC8.1(8)
SIG999: IC80.NTC R807.2
SIG1111: Q80.G R802.2 R803.2
SIGN284: IC13.3 R194.1
SIGN287: IC14.3 R195.1
SIGN289: IC16.3 R197.1
SIGN291: IC15.3 R196.1
SIGN304: IC21.2 R153.1 R186.1
SIGN305: IC22.2 R154.1 R188.1
SIGN314: IC23.2 R155.1 R190.1
SIGN315: IC24.2 R156.1 R192.1
SIGN366: HS1.1 R220.2
SIGN369: HS2.1 R221.2
SIGN371: HS3.1 R222.2
SIGN373: HS4.1 R223.2
N11927: Q15.4 Q16.4 Q17.4 Q18.4 R6.2 TP28.1
N66342: D80.A Q80.D T8.3(6) TP80.1
N66362: Q80.S R803.1 R804.2 R812.2 R813.2 R814.2
N14550647: C812.2 IC80.VS R808.1 R809.2
N14553110: D90.A D91.A D92.A T8.12(4) T8.13(6)
N14557584: C800.2 C801.1 C807.1 F8.2 IC80.HV R800.2 T8.1(6)
N14557692: C802.2 IC80.VDD R806.2
N14565222: IC80.DRV R802.1
N14565783: C803.2 IC80.CS R804.1
N14565980: D82.A T8.5(6)
N16785059: C801.2 C807.2 D80.C R800.1
N16790081: C810.1 R801.1

Not connected (* = marked no-connect by the designer): D84 NC; IC13 2; IC14 2; IC15 2; IC16 2; IC21 1; IC22 1; IC23 1; IC24 1; T8 2 7 10 11 14

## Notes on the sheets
sheet 1
- 3216
- 3216
- 3216
- 1005
- 3225
- 3216
- 1608
- 3216
- 1608
- NOT MOUNT
- 1608
- 1608
- 1608
- 3216
- 1005
- 1608
- 2012
- 1005
- 3216
- 3216
- 3216
- 1608
- 48V output
- for Fan power supply
- 1608
- 1005
- Housing(for CN8)
  :51191-0200
- for Fan power supply
- 1608
- Housing(for CN9)
  :51191-0200
- 1608
- 1608
- 2012
- 2012
- 1005
- 2012
- 1608
- 1608
sheet 2
- 1608
- 1608
- 1608
- 1608
- 1608
- 1608
- 1608
- 1608
- 1608
- 1608
- 1608
- 1005
- 1608
- 1005
- 1608
- 1608
- 1608
- 1608
- 1608
- 1608
- 1005
- 1005
- 1608
- 1608
- 1608
- 1608
- 1608
- 1608
- 1005
- 1005
- 1608
- 1608
- 1608
- 1608
- 1608
- 1608
- 1005
- 1005
